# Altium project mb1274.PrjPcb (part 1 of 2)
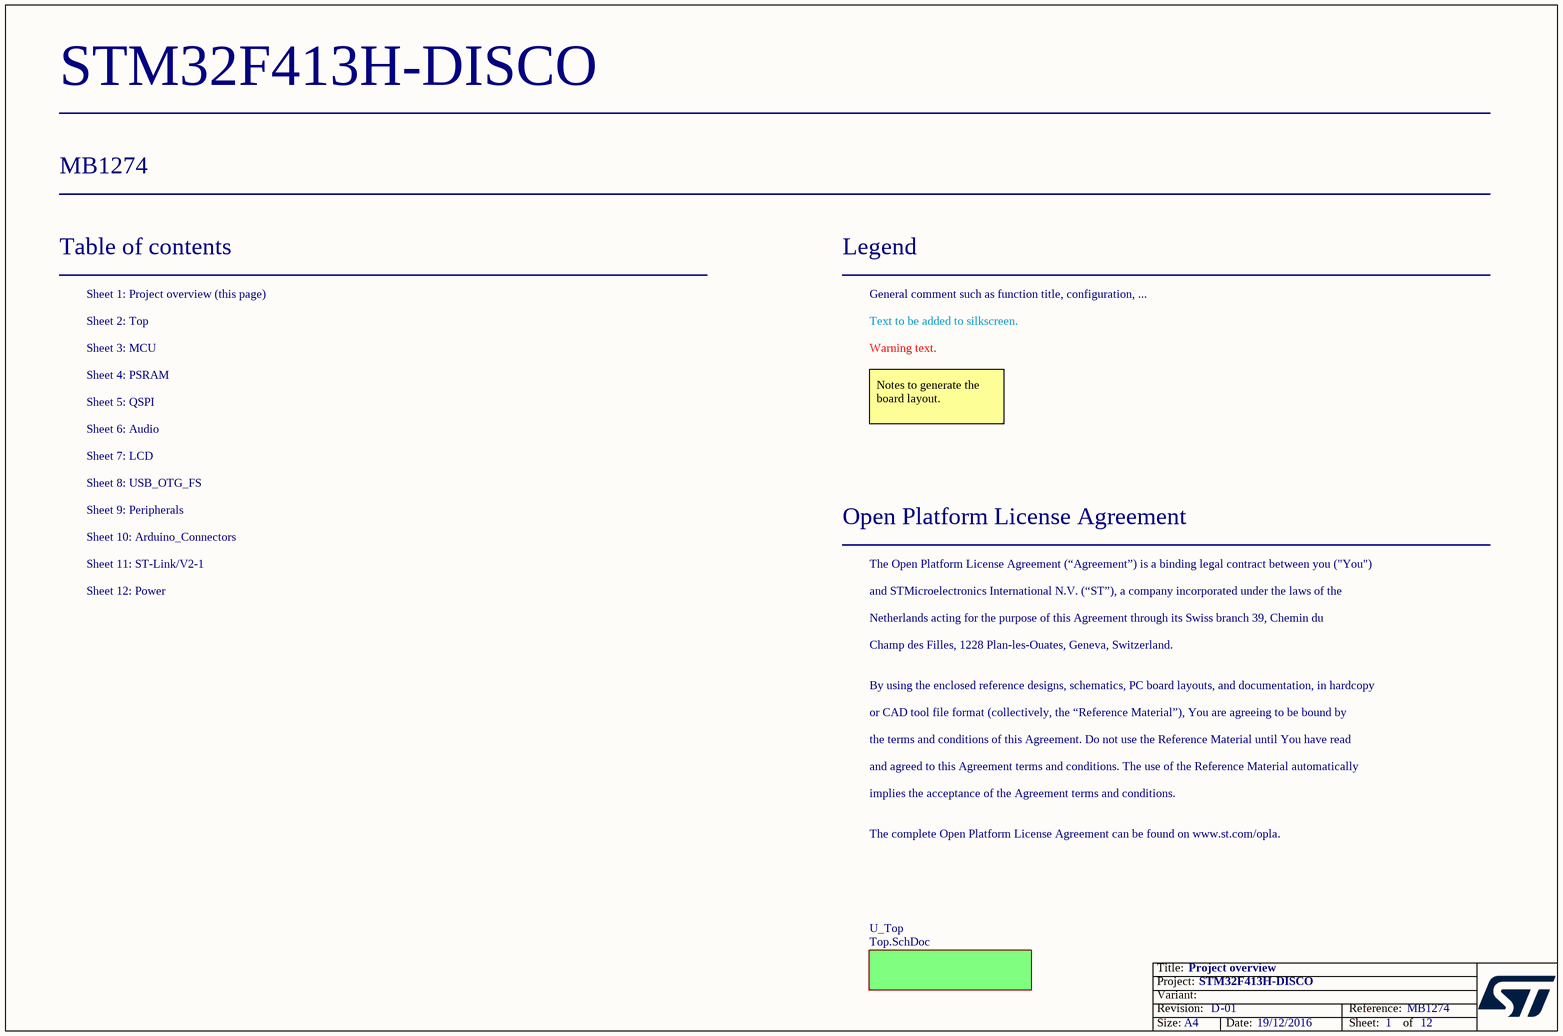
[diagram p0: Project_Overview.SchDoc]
Board_Assembly_Revision: 01; Board_Document_Date: 19/12/2016; Board_name: STM32F413H-DISCO; Board_PCB_Revision: D; Board_Reference: MB1274
12 sheets, 338 parts. Net scope: flat (ports and power ports of the same name join across sheets).
Sheets:
  Project_Overview.SchDoc
    U_Top = Top.SchDoc
      U_00_MCU = 00_MCU.SchDoc
      U_01_PSRAM = 01_PSRAM.SchDoc
      U_02_QSPI = 02_QSPI.SchDoc
      U_04_LCD = 04_LCD.SchDoc
      U_03_Audio = 03_Audio.SchDoc
      U_05_USB_OTG_FS = 05_USB_OTG_FS.SchDoc
      U_06_Peripherals = 06_Peripherals.SchDoc
      U_07_Arduino_ Connectors = 07_Arduino_ Connectors.SchDoc
      U_08_ST_LINK_V2-1 = 08_ST_LINK_V2-1.SCHDOC
      U_09_Power = 09_Power.SchDoc

## Sheet Project_Overview.SchDoc: Project overview
size A4; Date: Not used; ApprovedBy: Not used; CheckedBy: Not used; Author: Not used; CompanyName: STMicroelectronics; DrawnBy: Not used; Engineer: Not used; Organization: Not used; Address1: Not used; Address2: Not used; Address3: Not used; Address4: Not used; DocumentNumber: 1; Revision: Not used; SheetNumber: 1; SheetTotal: 12

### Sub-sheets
U_Top = Top.SchDoc: no entries

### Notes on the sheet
- Table of contents
- Sheet 1: Project overview (this page)
- Legend
- General comment such as function title, configuration, ...
- Sheet 2: Top
- Sheet 3: MCU
- Sheet 4: PSRAM
- Text to be added to silkscreen.
- Warning text.
- Sheet 6: Audio
- Sheet 5: QSPI
- Notes to generate the board layout.
- Sheet 7: LCD
- Sheet 8: USB_OTG_FS
- Sheet 9: Peripherals
- Sheet 11: ST-Link/V2-1
- Sheet 10: Arduino_Connectors
- Open Platform License Agreement
- The Open Platform License Agreement (“Agreement”) is a binding legal contract between you ("You")
- Sheet 12: Power
- and STMicroelectronics International N.V. (“ST”), a company incorporated under the laws of the
- Netherlands acting for the purpose of this Agreement through its Swiss branch 39, Chemin du
- Champ des Filles, 1228 Plan-les-Ouates, Geneva, Switzerland.
- By using the enclosed reference designs, schematics, PC board layouts, and documentation, in hardcopy
- or CAD tool file format (collectively, the “Reference Material”), You are agreeing to be bound by
- the terms and conditions of this Agreement. Do not use the Reference Material until You have read
- and agreed to this Agreement terms and conditions. The use of the Reference Material automatically
- implies the acceptance of the Agreement terms and conditions.
- The complete Open Platform License Agreement can be found on www.st.com/opla.

## Sheet Top.SchDoc: MB1274-TOP
size A3; Date: 3/31/2015; Author: P.A.; CompanyName: STMicroelectronics; Organization: Microcontrollers Division; Address1: 12, Rue Jules HOROWITZ; Address2: 38019 Grenoble; Address3: FRANCE; DocumentNumber: 2; Revision: D-01; SheetNumber: 2; SheetTotal: 12; Project: STM32F413H-DISCO
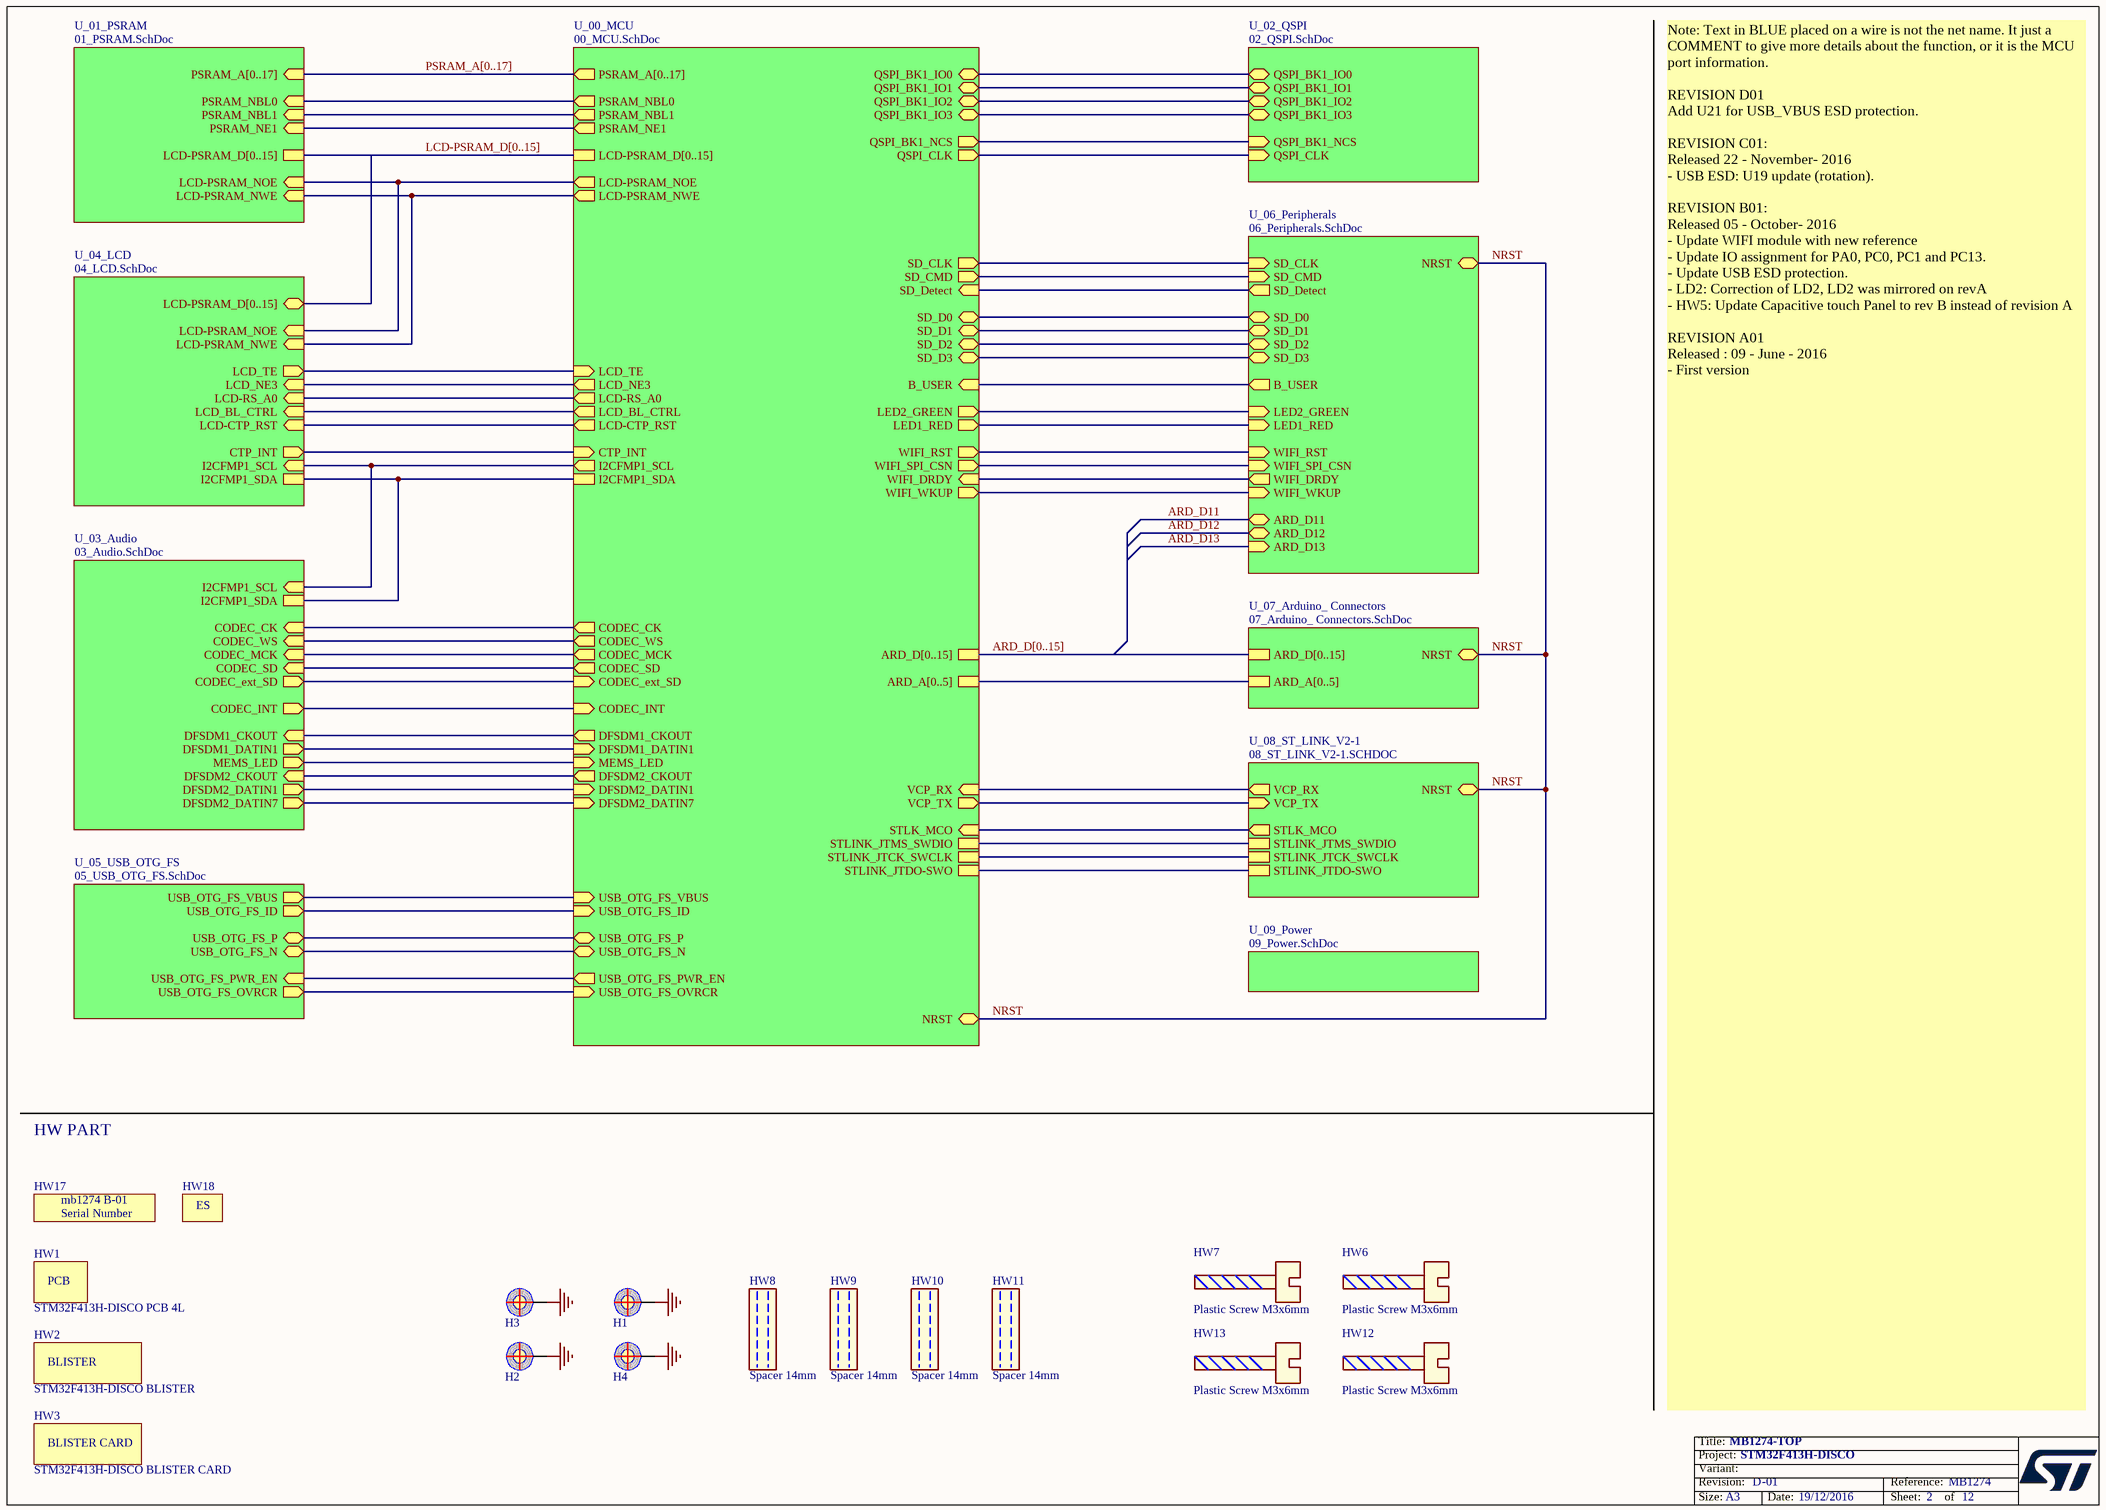
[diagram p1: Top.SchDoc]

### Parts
H1  POSITION HOLE C6D3R5  [PTH_M1261-3005-N_3P5X6_M3_H14]  (value not drawn)
H2  POSITION HOLE C6D3R5  [PTH_M1261-3005-N_3P5X6_M3_H14]  (value not drawn)
H3  POSITION HOLE C6D3R5  [PTH_M1261-3005-N_3P5X6_M3_H14]  (value not drawn)
H4  POSITION HOLE C6D3R5  [PTH_M1261-3005-N_3P5X6_M3_H14]  (value not drawn)
HW1  STM32F413H-DISCO PCB 4L  (mechanical)
HW2  STM32F413H-DISCO BLISTER  (mechanical)
HW3  STM32F413H-DISCO BLISTER CARD  (mechanical)
HW6  Plastic Screw M3x6mm  (mechanical)
HW7  Plastic Screw M3x6mm  (mechanical)
HW8  Spacer 14mm  (mechanical)
HW9  Spacer 14mm  (mechanical)
HW10  Spacer 14mm  (mechanical)
HW11  Spacer 14mm  (mechanical)
HW12  Plastic Screw M3x6mm  (mechanical)
HW13  Plastic Screw M3x6mm  (mechanical)
HW17  mb1274 B-01 + SN  (value not drawn)  (mechanical)
HW18  ES  (value not drawn)  (mechanical)

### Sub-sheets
U_00_MCU = 00_MCU.SchDoc: NRST (bidir), QSPI_BK1_IO3 (bidir), QSPI_BK1_IO2 (bidir), QSPI_BK1_IO0 (bidir), QSPI_BK1_IO1 (bidir), QSPI_CLK (out), QSPI_BK1_NCS (out), USB_OTG_FS_OVRCR (in), USB_OTG_FS_PWR_EN (out), B_USER (in), STLK_MCO (in), CODEC_INT (in), LCD_TE (in), LCD_BL_CTRL (out), PSRAM_A[0..17] (out), LCD-PSRAM_D[0..15], LCD-PSRAM_NWE (out), LCD-PSRAM_NOE (out), PSRAM_NE1 (out), PSRAM_NBL0 (out), PSRAM_NBL1 (out), LCD_NE3 (out), LCD-CTP_RST (out), CTP_INT (in), LED1_RED (out), LED2_GREEN (out), USB_OTG_FS_VBUS (in), USB_OTG_FS_ID (in), I2CFMP1_SDA, I2CFMP1_SCL (out), USB_OTG_FS_N (bidir), USB_OTG_FS_P (bidir), STLINK_JTMS_SWDIO, STLINK_JTCK_SWCLK, STLINK_JTDO-SWO, LCD-RS_A0 (out), SD_D2 (bidir), WIFI_SPI_CSN (out), DFSDM2_DATIN7 (in), WIFI_DRDY (in), SD_D3 (bidir), SD_CLK (out), DFSDM1_DATIN1 (in), DFSDM2_DATIN1 (in), DFSDM1_CKOUT (out), SD_Detect (in), SD_CMD (out), SD_D0 (bidir), SD_D1 (bidir), DFSDM2_CKOUT (out), CODEC_WS (out), CODEC_CK (out), CODEC_SD (out), CODEC_MCK (out), CODEC_ext_SD (in), ARD_A[0..5], ARD_D[0..15], VCP_TX (out), VCP_RX (in), WIFI_WKUP (out), MEMS_LED (in), WIFI_RST (out)
U_01_PSRAM = 01_PSRAM.SchDoc: PSRAM_A[0..17] (in), LCD-PSRAM_D[0..15], LCD-PSRAM_NWE (in), LCD-PSRAM_NOE (in), PSRAM_NE1 (in), PSRAM_NBL0 (in), PSRAM_NBL1 (in)
U_02_QSPI = 02_QSPI.SchDoc: QSPI_BK1_IO0 (bidir), QSPI_BK1_IO2 (bidir), QSPI_BK1_IO1 (bidir), QSPI_BK1_IO3 (bidir), QSPI_CLK (in), QSPI_BK1_NCS (in)
U_03_Audio = 03_Audio.SchDoc: CODEC_INT (out), I2CFMP1_SCL (in), I2CFMP1_SDA, DFSDM1_DATIN1 (out), DFSDM1_CKOUT (in), DFSDM2_CKOUT (in), DFSDM2_DATIN1 (out), DFSDM2_DATIN7 (out), CODEC_CK (in), CODEC_WS (in), CODEC_SD (in), CODEC_ext_SD (out), CODEC_MCK (in), MEMS_LED (out)
U_04_LCD = 04_LCD.SchDoc: LCD_BL_CTRL (in), CTP_INT (out), LCD_TE (out), LCD-CTP_RST (in), LCD_NE3 (in), LCD-PSRAM_D[0..15] (bidir), LCD-PSRAM_NWE (in), LCD-PSRAM_NOE (in), LCD-RS_A0 (in), I2CFMP1_SDA, I2CFMP1_SCL (in)
U_05_USB_OTG_FS = 05_USB_OTG_FS.SchDoc: USB_OTG_FS_VBUS (out), USB_OTG_FS_ID (out), USB_OTG_FS_PWR_EN (in), USB_OTG_FS_OVRCR (out), USB_OTG_FS_N (bidir), USB_OTG_FS_P (bidir)
U_06_Peripherals = 06_Peripherals.SchDoc: LED1_RED (in), LED2_GREEN (in), NRST (bidir), B_USER (out), SD_CLK (in), SD_CMD (in), SD_D0 (bidir), SD_D1 (bidir), SD_D2 (bidir), SD_D3 (bidir), SD_Detect (out), WIFI_SPI_CSN (in), WIFI_DRDY (out), WIFI_RST (in), WIFI_WKUP (in), ARD_D11 (bidir), ARD_D12 (bidir), ARD_D13 (in)
U_07_Arduino_ Connectors = 07_Arduino_ Connectors.SchDoc: NRST (bidir), ARD_A[0..5], ARD_D[0..15]
U_08_ST_LINK_V2-1 = 08_ST_LINK_V2-1.SCHDOC: NRST (bidir), STLINK_JTDO-SWO, STLK_MCO (out), STLINK_JTMS_SWDIO, STLINK_JTCK_SWCLK, VCP_RX (out), VCP_TX (in)
U_09_Power = 09_Power.SchDoc: no entries

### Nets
GND: H1.1 H2.1 H3.1 H4.1
NRST: sheet U_00_MCU/NRST, sheet U_06_Peripherals/NRST, sheet U_07_Arduino_ Connectors/NRST, sheet U_08_ST_LINK_V2-1/NRST
(unnamed): sheet U_00_MCU/QSPI_BK1_IO3, sheet U_02_QSPI/QSPI_BK1_IO3
(unnamed): sheet U_00_MCU/QSPI_BK1_IO2, sheet U_02_QSPI/QSPI_BK1_IO2  [a separate net that carries the same name]
(unnamed): sheet U_00_MCU/QSPI_BK1_IO0, sheet U_02_QSPI/QSPI_BK1_IO0  [a separate net that carries the same name]
(unnamed): sheet U_00_MCU/QSPI_BK1_IO1, sheet U_02_QSPI/QSPI_BK1_IO1  [a separate net that carries the same name]
(unnamed): sheet U_00_MCU/QSPI_CLK, sheet U_02_QSPI/QSPI_CLK  [a separate net that carries the same name]
(unnamed): sheet U_00_MCU/QSPI_BK1_NCS, sheet U_02_QSPI/QSPI_BK1_NCS  [a separate net that carries the same name]
(unnamed): sheet U_00_MCU/USB_OTG_FS_OVRCR, sheet U_05_USB_OTG_FS/USB_OTG_FS_OVRCR  [a separate net that carries the same name]
(unnamed): sheet U_00_MCU/USB_OTG_FS_PWR_EN, sheet U_05_USB_OTG_FS/USB_OTG_FS_PWR_EN  [a separate net that carries the same name]
(unnamed): sheet U_00_MCU/B_USER, sheet U_06_Peripherals/B_USER  [a separate net that carries the same name]
(unnamed): sheet U_00_MCU/STLK_MCO, sheet U_08_ST_LINK_V2-1/STLK_MCO  [a separate net that carries the same name]
(unnamed): sheet U_00_MCU/CODEC_INT, sheet U_03_Audio/CODEC_INT  [a separate net that carries the same name]
(unnamed): sheet U_00_MCU/LCD_TE, sheet U_04_LCD/LCD_TE  [a separate net that carries the same name]
(unnamed): sheet U_00_MCU/LCD_BL_CTRL, sheet U_04_LCD/LCD_BL_CTRL  [a separate net that carries the same name]
(unnamed): sheet U_00_MCU/LCD-PSRAM_NWE, sheet U_01_PSRAM/LCD-PSRAM_NWE, sheet U_04_LCD/LCD-PSRAM_NWE  [a separate net that carries the same name]
(unnamed): sheet U_00_MCU/LCD-PSRAM_NOE, sheet U_01_PSRAM/LCD-PSRAM_NOE, sheet U_04_LCD/LCD-PSRAM_NOE  [a separate net that carries the same name]
(unnamed): sheet U_00_MCU/PSRAM_NE1, sheet U_01_PSRAM/PSRAM_NE1  [a separate net that carries the same name]
(unnamed): sheet U_00_MCU/PSRAM_NBL0, sheet U_01_PSRAM/PSRAM_NBL0  [a separate net that carries the same name]
(unnamed): sheet U_00_MCU/PSRAM_NBL1, sheet U_01_PSRAM/PSRAM_NBL1  [a separate net that carries the same name]
(unnamed): sheet U_00_MCU/LCD_NE3, sheet U_04_LCD/LCD_NE3  [a separate net that carries the same name]
(unnamed): sheet U_00_MCU/LCD-CTP_RST, sheet U_04_LCD/LCD-CTP_RST  [a separate net that carries the same name]
(unnamed): sheet U_00_MCU/CTP_INT, sheet U_04_LCD/CTP_INT  [a separate net that carries the same name]
(unnamed): sheet U_00_MCU/LED1_RED, sheet U_06_Peripherals/LED1_RED  [a separate net that carries the same name]
(unnamed): sheet U_00_MCU/LED2_GREEN, sheet U_06_Peripherals/LED2_GREEN  [a separate net that carries the same name]
(unnamed): sheet U_00_MCU/USB_OTG_FS_VBUS, sheet U_05_USB_OTG_FS/USB_OTG_FS_VBUS  [a separate net that carries the same name]
(unnamed): sheet U_00_MCU/USB_OTG_FS_ID, sheet U_05_USB_OTG_FS/USB_OTG_FS_ID  [a separate net that carries the same name]
(unnamed): sheet U_00_MCU/I2CFMP1_SDA, sheet U_04_LCD/I2CFMP1_SDA, sheet U_03_Audio/I2CFMP1_SDA  [a separate net that carries the same name]
(unnamed): sheet U_00_MCU/I2CFMP1_SCL, sheet U_04_LCD/I2CFMP1_SCL, sheet U_03_Audio/I2CFMP1_SCL  [a separate net that carries the same name]
(unnamed): sheet U_00_MCU/USB_OTG_FS_N, sheet U_05_USB_OTG_FS/USB_OTG_FS_N  [a separate net that carries the same name]
(unnamed): sheet U_00_MCU/USB_OTG_FS_P, sheet U_05_USB_OTG_FS/USB_OTG_FS_P  [a separate net that carries the same name]
(unnamed): sheet U_00_MCU/STLINK_JTMS_SWDIO, sheet U_08_ST_LINK_V2-1/STLINK_JTMS_SWDIO  [a separate net that carries the same name]
(unnamed): sheet U_00_MCU/STLINK_JTCK_SWCLK, sheet U_08_ST_LINK_V2-1/STLINK_JTCK_SWCLK  [a separate net that carries the same name]
(unnamed): sheet U_00_MCU/STLINK_JTDO-SWO, sheet U_08_ST_LINK_V2-1/STLINK_JTDO-SWO  [a separate net that carries the same name]
(unnamed): sheet U_00_MCU/LCD-RS_A0, sheet U_04_LCD/LCD-RS_A0  [a separate net that carries the same name]
(unnamed): sheet U_00_MCU/SD_D2, sheet U_06_Peripherals/SD_D2  [a separate net that carries the same name]
(unnamed): sheet U_00_MCU/WIFI_SPI_CSN, sheet U_06_Peripherals/WIFI_SPI_CSN  [a separate net that carries the same name]
(unnamed): sheet U_00_MCU/DFSDM2_DATIN7, sheet U_03_Audio/DFSDM2_DATIN7  [a separate net that carries the same name]
(unnamed): sheet U_00_MCU/WIFI_DRDY, sheet U_06_Peripherals/WIFI_DRDY  [a separate net that carries the same name]
(unnamed): sheet U_00_MCU/SD_D3, sheet U_06_Peripherals/SD_D3  [a separate net that carries the same name]
(unnamed): sheet U_00_MCU/SD_CLK, sheet U_06_Peripherals/SD_CLK  [a separate net that carries the same name]
(unnamed): sheet U_00_MCU/DFSDM1_DATIN1, sheet U_03_Audio/DFSDM1_DATIN1  [a separate net that carries the same name]
(unnamed): sheet U_00_MCU/DFSDM2_DATIN1, sheet U_03_Audio/DFSDM2_DATIN1  [a separate net that carries the same name]
(unnamed): sheet U_00_MCU/DFSDM1_CKOUT, sheet U_03_Audio/DFSDM1_CKOUT  [a separate net that carries the same name]
(unnamed): sheet U_00_MCU/SD_Detect, sheet U_06_Peripherals/SD_Detect  [a separate net that carries the same name]
(unnamed): sheet U_00_MCU/SD_CMD, sheet U_06_Peripherals/SD_CMD  [a separate net that carries the same name]
(unnamed): sheet U_00_MCU/SD_D0, sheet U_06_Peripherals/SD_D0  [a separate net that carries the same name]
(unnamed): sheet U_00_MCU/SD_D1, sheet U_06_Peripherals/SD_D1  [a separate net that carries the same name]
(unnamed): sheet U_00_MCU/DFSDM2_CKOUT, sheet U_03_Audio/DFSDM2_CKOUT  [a separate net that carries the same name]
(unnamed): sheet U_00_MCU/CODEC_WS, sheet U_03_Audio/CODEC_WS  [a separate net that carries the same name]
(unnamed): sheet U_00_MCU/CODEC_CK, sheet U_03_Audio/CODEC_CK  [a separate net that carries the same name]
(unnamed): sheet U_00_MCU/CODEC_SD, sheet U_03_Audio/CODEC_SD  [a separate net that carries the same name]
(unnamed): sheet U_00_MCU/CODEC_MCK, sheet U_03_Audio/CODEC_MCK  [a separate net that carries the same name]
(unnamed): sheet U_00_MCU/CODEC_ext_SD, sheet U_03_Audio/CODEC_ext_SD  [a separate net that carries the same name]
(unnamed): sheet U_00_MCU/VCP_TX, sheet U_08_ST_LINK_V2-1/VCP_TX  [a separate net that carries the same name]
(unnamed): sheet U_00_MCU/VCP_RX, sheet U_08_ST_LINK_V2-1/VCP_RX  [a separate net that carries the same name]
(unnamed): sheet U_00_MCU/WIFI_WKUP, sheet U_06_Peripherals/WIFI_WKUP  [a separate net that carries the same name]
(unnamed): sheet U_00_MCU/MEMS_LED, sheet U_03_Audio/MEMS_LED  [a separate net that carries the same name]
(unnamed): sheet U_00_MCU/WIFI_RST, sheet U_06_Peripherals/WIFI_RST  [a separate net that carries the same name]

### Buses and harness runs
bus ARD_D[0..15] = sheet U_00_MCU/ARD_D[0..15] = sheet U_07_Arduino_ Connectors/ARD_D[0..15]
bus LCD-PSRAM_D[0..15] = sheet U_00_MCU/LCD-PSRAM_D[0..15] = sheet U_01_PSRAM/LCD-PSRAM_D[0..15] = sheet U_04_LCD/LCD-PSRAM_D[0..15]
bus PSRAM_A[0..17] = sheet U_00_MCU/PSRAM_A[0..17] = sheet U_01_PSRAM/PSRAM_A[0..17]
bus sheet U_00_MCU/ARD_A[0..5] = sheet U_07_Arduino_ Connectors/ARD_A[0..5]

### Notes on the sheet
- HW PART
- Note: Text in BLUE placed on a wire is not the net name. It just a COMMENT to give more details about the function, or it is the MCU port information.
  REVISION D01
  Add U21 for USB_VBUS ESD protection.
  REVISION C01:
  Released 22 - November- 2016
  - USB ESD: U19 update (rotation).
  REVISION B01:
  Released 05 - October- 2016
  - Update WIFI module with new reference
  - Update IO assignment for PA0, PC0, PC1 and PC13.
  - Update USB ESD protection.
  - LD2: Correction of LD2, LD2 was mirrored on revA
  - HW5: Update Capacitive touch Panel to rev B instead of revision A
  REVISION A01
  Released : 09 - June - 2016
  - First version

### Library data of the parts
HW1 = PCB: Fitted: YES; Ordered_By: Subcon
HW2 = BLISTER: Fitted: YES; Ordered_By: Subcon
HW3 = BLISTER CARD: Ordered_By: subcon; Fitted: YES
HW6 HW7 HW12 HW13 = Plastic Screw M3x6mm: Plastic screw; Ordered_By: Subcon; Fitted: Manually
HW8-HW11 = Plastic Spacer D4.5x14, M3x0.5: Plastic spacer; Manuf_1: RAF; Manuf_Part_1: M1261-3005-N; Ordered_By: Subcon; Fitted: Manually
HW17 = STICKER_SN_number: Sticker for Board SN number; Ordered_By: Subcon; Fitted: YES
HW18 = STICKER_ES: Sticker for ES sample; Ordered_By: Subcon; Fitted: YES

## Sheet 00_MCU.SchDoc: MCU
size A3; Date: 3/31/2015; Author: P.A.; CompanyName: STMicroelectronics; Organization: Microcontrollers Division; Address1: 12, Rue Jules HOROWITZ; Address2: 38019 Grenoble; Address3: FRANCE; DocumentNumber: 3; Revision: D-01; SheetNumber: 3; SheetTotal: 12; Project: STM32F413H-DISCO
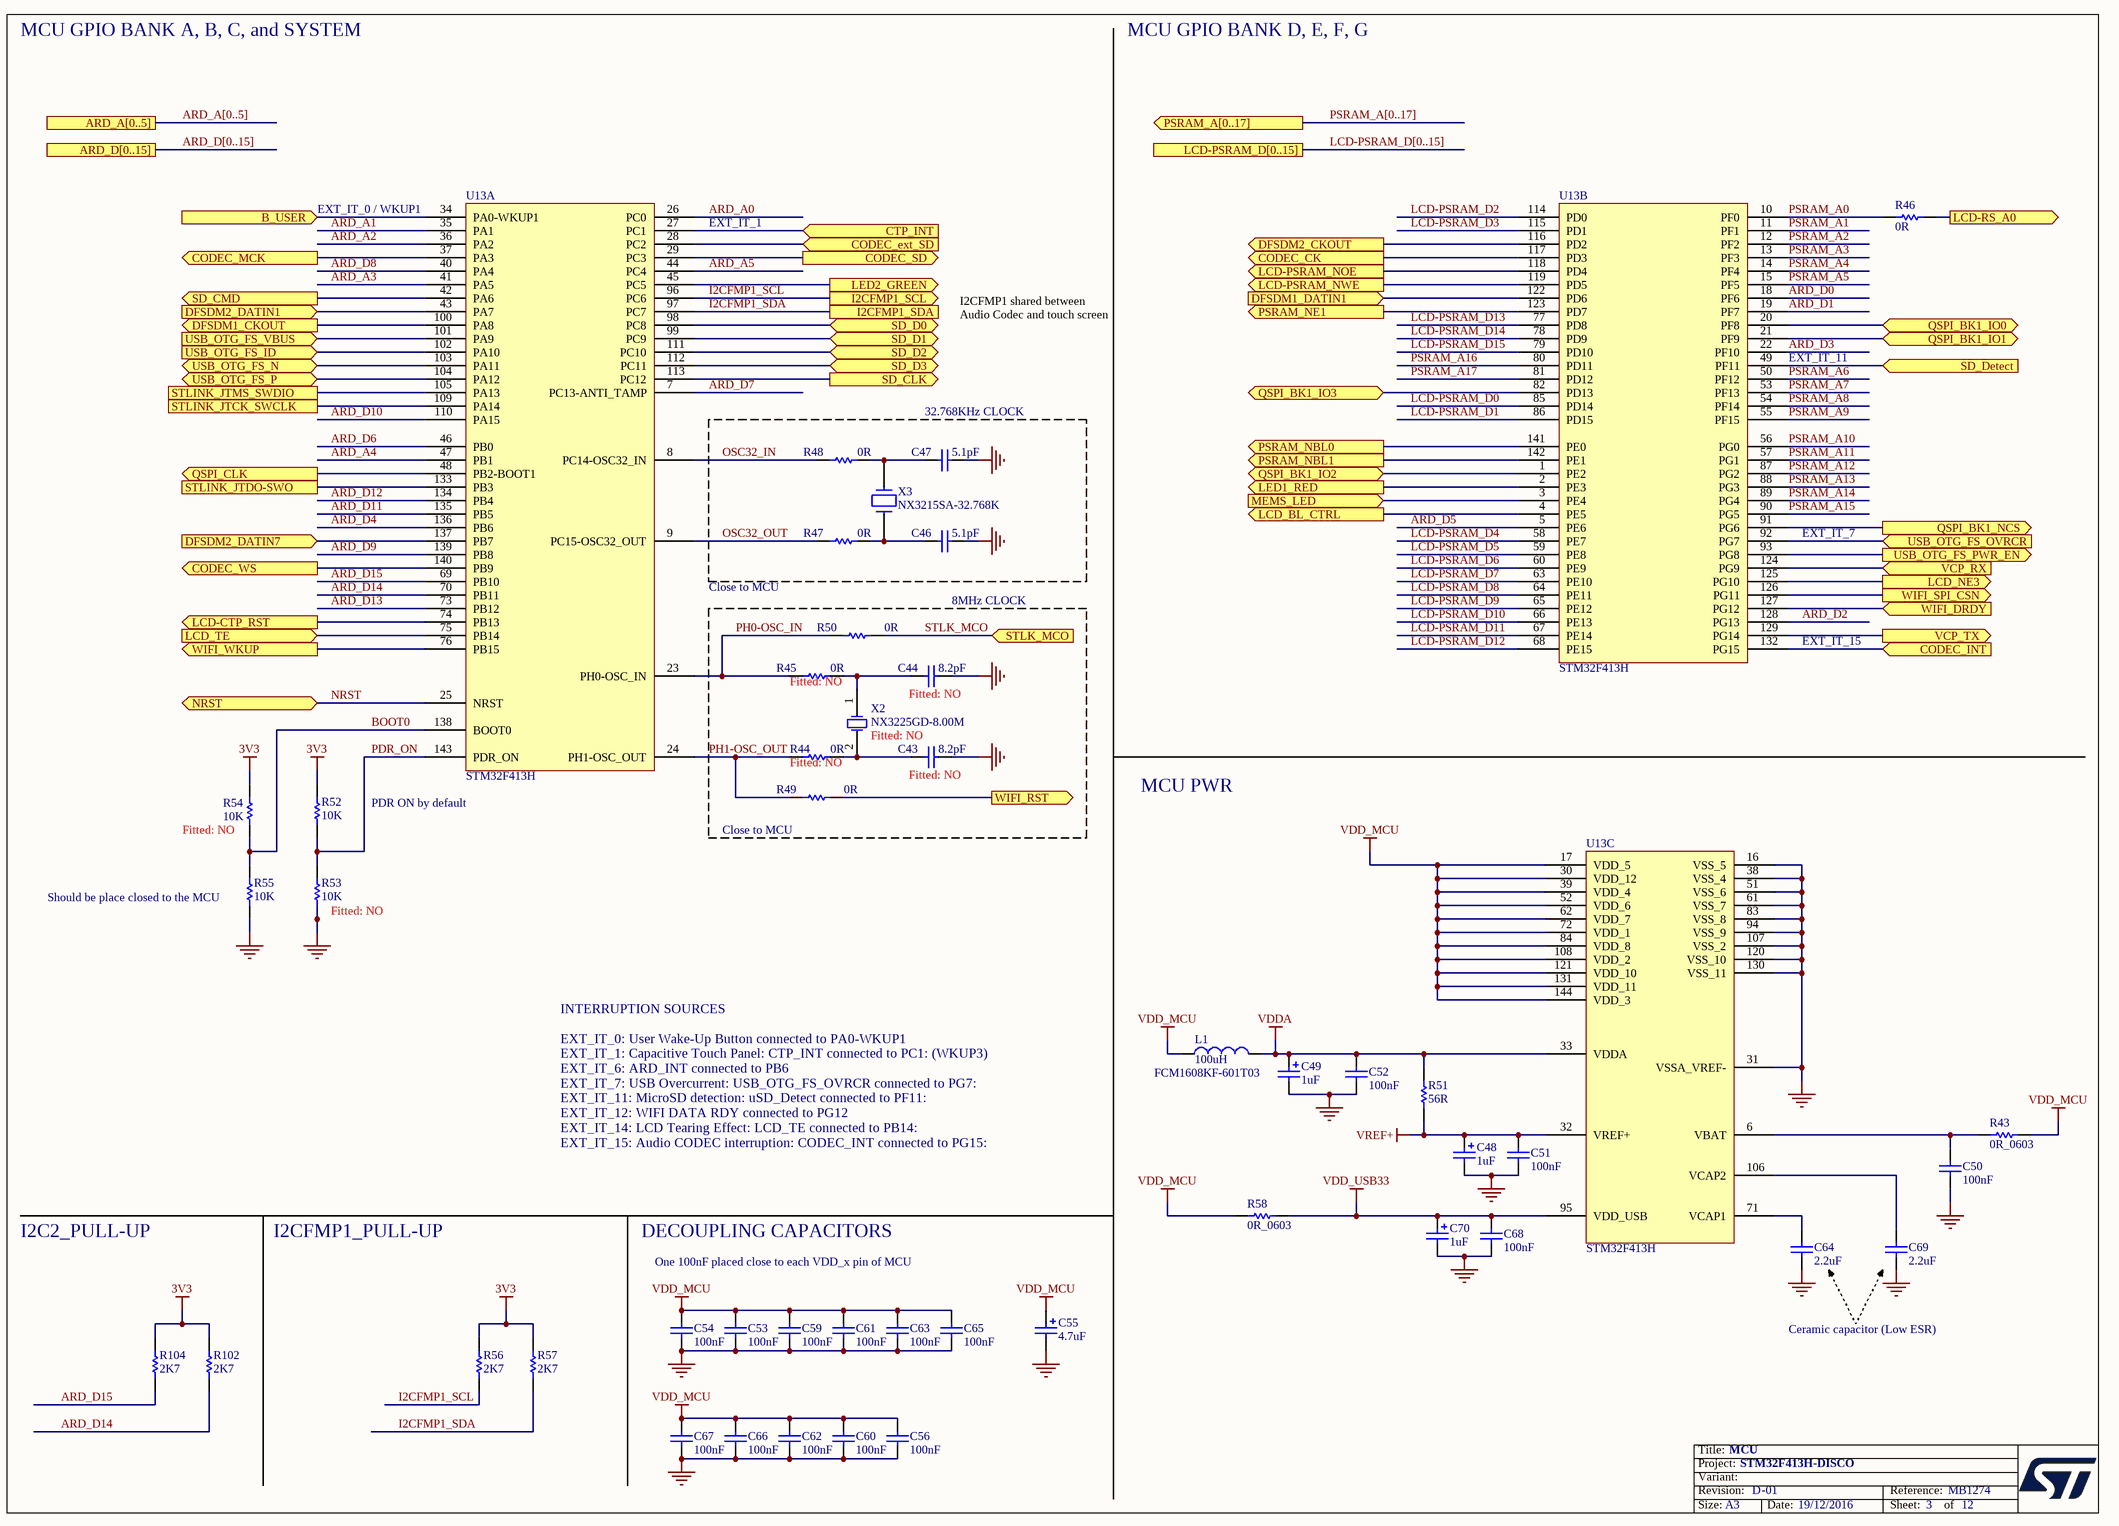
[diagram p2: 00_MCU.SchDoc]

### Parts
C43  8.2pF  Fitted: NO  [C0402]
C44  8.2pF  Fitted: NO  [C0402]
C46  5.1pF  [C0402]
C47  5.1pF  [C0402]
C48  1uF  [CPOL_TAJ-A_1206_H180]
C49  1uF  [CPOL_TAJ-A_1206_H180]
C50  100nF  [C0402]
C51  100nF  [C0402]
C52  100nF  [C0402]
C53  100nF  [C0402]
C54  100nF  [C0402]
C55  4.7uF  [CPOL_TAJ-A_1206_H180]
C56  100nF  [C0402]
C59  100nF  [C0402]
C60  100nF  [C0402]
C61  100nF  [C0402]
C62  100nF  [C0402]
C63  100nF  [C0402]
C64  2.2uF  [C1206]
C65  100nF  [C0402]
C66  100nF  [C0402]
C67  100nF  [C0402]
C68  100nF  [C0402]
C69  2.2uF  [C1206]
C70  1uF  [CPOL_TAJ-A_1206_H180]
L1  100uH  Manuf_Part_1: FCM1608KF-601T03  [L0603]
R43  0R_0603  [R0603]
R44  0R  Fitted: NO  [R0402]
R45  0R  Fitted: NO  [R0402]
R46  0R  [R0402]
R47  0R  [R0402]
R48  0R  [R0402]
R49  0R  [R0402]
R50  0R  [R0402]
R51  56R  [R0402]
R52  10K  [R0402]
R53  10K  Fitted: NO  [R0402]
R54  10K  Fitted: NO  [R0402]
R55  10K  [R0402]
R56  2K7  [R0402]
R57  2K7  [R0402]
R58  0R_0603  [R0603]
R102  2K7  [R0402]
R104  2K7  [R0402]
U13  STM32F413H  [ICC_LQFP144_20X20_P050]  (parts A,B,C of 3)
X2  NX3225GD-8.00M  Fitted: NO  [CRY_NX3225GD_2P]
X3  NX3215SA-32.768K  [CRY_NX3215SA_2P]

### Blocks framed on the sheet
32.768KHz CLOCK: C46 C47 R47 R48 X3

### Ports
ARD_A[0..5], ARD_D[0..15], B_USER (in), CODEC_CK (out), CODEC_ext_SD (in), CODEC_INT (in), CODEC_MCK (out), CODEC_SD (out), CODEC_WS (out), CTP_INT (in), DFSDM1_CKOUT (out), DFSDM1_DATIN1 (in), DFSDM2_CKOUT (out), DFSDM2_DATIN1 (in), DFSDM2_DATIN7 (in), I2CFMP1_SCL (out), I2CFMP1_SDA, LCD-CTP_RST (out), LCD-PSRAM_D[0..15], LCD-PSRAM_NOE (out), LCD-PSRAM_NWE (out), LCD-RS_A0 (out), LCD_BL_CTRL (out), LCD_NE3 (out), LCD_TE (in), LED1_RED (out), LED2_GREEN (out), MEMS_LED (in), NRST (bidir), PSRAM_A[0..17] (out), PSRAM_NBL0 (out), PSRAM_NBL1 (out), PSRAM_NE1 (out), QSPI_BK1_IO0 (bidir), QSPI_BK1_IO1 (bidir), QSPI_BK1_IO2 (bidir), QSPI_BK1_IO3 (bidir), QSPI_BK1_NCS (out), QSPI_CLK (out), SD_CLK (out), SD_CMD (out), SD_D0 (bidir), SD_D1 (bidir), SD_D2 (bidir), SD_D3 (bidir), SD_Detect (in), STLINK_JTCK_SWCLK, STLINK_JTDO-SWO, STLINK_JTMS_SWDIO, STLK_MCO (in), USB_OTG_FS_ID (in), USB_OTG_FS_N (bidir), USB_OTG_FS_OVRCR (in), USB_OTG_FS_P (bidir), USB_OTG_FS_PWR_EN (out), USB_OTG_FS_VBUS (in), VCP_RX (in), VCP_TX (out), WIFI_DRDY (in), WIFI_RST (out), WIFI_SPI_CSN (out), WIFI_WKUP (out)

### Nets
3V3: R52.2 R54.1 R56.2 R57.2 R102.2 R104.2
GND: C43.2 C44.2 C46.2 C47.2 C48.2 C49.2 C50.1 C51.1 C52.1 C53.1 C54.1 C55.2 C56.1 C59.1 C60.1 C61.1 C62.1 C63.1 C64.1 C65.1 C66.1 C67.1 C68.1 C69.1 C70.2 R53.1 R55.1 U13.16(VSS_5) U13.31(VSSA_VREF-) U13.38(VSS_4) U13.51(VSS_6) U13.61(VSS_7) U13.83(VSS_8) U13.94(VSS_9) U13.107(VSS_2) U13.120(VSS_10) U13.130(VSS_11)
VDD_MCU: C53.2 C54.2 C55.1 C56.2 C59.2 C60.2 C61.2 C62.2 C63.2 C65.2 C66.2 C67.2 L1.1 R43.2 R58.1 U13.17(VDD_5) U13.30(VDD_12) U13.39(VDD_4) U13.52(VDD_6) U13.62(VDD_7) U13.72(VDD_1) U13.84(VDD_8) U13.108(VDD_2) U13.121(VDD_10) U13.131(VDD_11) U13.144(VDD_3)
VDD_USB33: C68.2 C70.1 R58.2 U13.95(VDD_USB)
VDDA: C49.1 C52.2 L1.2 R51.2 U13.33(VDDA)
VREF+: C48.1 C51.2 R51.1 U13.32(VREF+)
ARD_A0: U13.26(PC0)
ARD_A1: U13.35(PA1)
ARD_A2: U13.36(PA2)
ARD_A3: U13.41(PA5)
ARD_A4: U13.47(PB1)
ARD_A5: U13.44(PC4)
ARD_D0: U13.18(PF6)
ARD_D1: U13.19(PF7)
ARD_D2: U13.128(PG13)
ARD_D3: U13.22(PF10)
ARD_D4: U13.136(PB6)
ARD_D5: U13.5(PE6)
ARD_D6: U13.46(PB0)
ARD_D7: U13.7(PC13-ANTI_TAMP)
ARD_D8: U13.40(PA4)
ARD_D9: U13.139(PB8)
ARD_D10: U13.110(PA15)
ARD_D11: U13.135(PB5)
ARD_D12: U13.134(PB4)
ARD_D13: U13.73(PB12)
ARD_D14: R102.1 U13.70(PB11)
ARD_D15: R104.1 U13.69(PB10)
B_USER: U13.34(PA0-WKUP1) ; port B_USER
BOOT0: R54.2 R55.2 U13.138(BOOT0)
CODEC_CK: U13.117(PD3) ; port CODEC_CK
CODEC_ext_SD: U13.28(PC2) ; port CODEC_ext_SD
CODEC_INT: U13.132(PG15) ; port CODEC_INT
CODEC_MCK: U13.37(PA3) ; port CODEC_MCK
CODEC_SD: U13.29(PC3) ; port CODEC_SD
CODEC_WS: U13.140(PB9) ; port CODEC_WS
CTP_INT: U13.27(PC1) ; port CTP_INT
DFSDM1_CKOUT: U13.100(PA8) ; port DFSDM1_CKOUT
DFSDM1_DATIN1: U13.122(PD6) ; port DFSDM1_DATIN1
DFSDM2_CKOUT: U13.116(PD2) ; port DFSDM2_CKOUT
DFSDM2_DATIN1: U13.43(PA7) ; port DFSDM2_DATIN1
DFSDM2_DATIN7: U13.137(PB7) ; port DFSDM2_DATIN7
I2CFMP1_SCL: R56.1 U13.96(PC6) ; port I2CFMP1_SCL
I2CFMP1_SDA: R57.1 U13.97(PC7) ; port I2CFMP1_SDA
LCD-CTP_RST: U13.74(PB13) ; port LCD-CTP_RST
LCD-PSRAM_D0: U13.85(PD14)
LCD-PSRAM_D1: U13.86(PD15)
LCD-PSRAM_D2: U13.114(PD0)
LCD-PSRAM_D3: U13.115(PD1)
LCD-PSRAM_D4: U13.58(PE7)
LCD-PSRAM_D5: U13.59(PE8)
LCD-PSRAM_D6: U13.60(PE9)
LCD-PSRAM_D7: U13.63(PE10)
LCD-PSRAM_D8: U13.64(PE11)
LCD-PSRAM_D9: U13.65(PE12)
LCD-PSRAM_D10: U13.66(PE13)
LCD-PSRAM_D11: U13.67(PE14)
LCD-PSRAM_D12: U13.68(PE15)
LCD-PSRAM_D13: U13.77(PD8)
LCD-PSRAM_D14: U13.78(PD9)
LCD-PSRAM_D15: U13.79(PD10)
LCD-PSRAM_NOE: U13.118(PD4) ; port LCD-PSRAM_NOE
LCD-PSRAM_NWE: U13.119(PD5) ; port LCD-PSRAM_NWE
LCD-RS_A0: R46.2 ; port LCD-RS_A0
LCD_BL_CTRL: U13.4(PE5) ; port LCD_BL_CTRL
LCD_NE3: U13.125(PG10) ; port LCD_NE3
LCD_TE: U13.75(PB14) ; port LCD_TE
LED1_RED: U13.2(PE3) ; port LED1_RED
LED2_GREEN: U13.45(PC5) ; port LED2_GREEN
MEMS_LED: U13.3(PE4) ; port MEMS_LED
NRST: U13.25(NRST) ; port NRST
OSC32_IN: R48.1 U13.8(PC14-OSC32_IN)
OSC32_OUT: R47.1 U13.9(PC15-OSC32_OUT)
PDR_ON: R52.1 R53.2 U13.143(PDR_ON)
PH0-OSC_IN: R45.1 R50.1 U13.23(PH0-OSC_IN)
PH1-OSC_OUT: R44.1 R49.1 U13.24(PH1-OSC_OUT)
PSRAM_A0: R46.1 U13.10(PF0)
PSRAM_A1: U13.11(PF1)
PSRAM_A2: U13.12(PF2)
PSRAM_A3: U13.13(PF3)
PSRAM_A4: U13.14(PF4)
PSRAM_A5: U13.15(PF5)
PSRAM_A6: U13.50(PF12)
PSRAM_A7: U13.53(PF13)
PSRAM_A8: U13.54(PF14)
PSRAM_A9: U13.55(PF15)
PSRAM_A10: U13.56(PG0)
PSRAM_A11: U13.57(PG1)
PSRAM_A12: U13.87(PG2)
PSRAM_A13: U13.88(PG3)
PSRAM_A14: U13.89(PG4)
PSRAM_A15: U13.90(PG5)
PSRAM_A16: U13.80(PD11)
PSRAM_A17: U13.81(PD12)
PSRAM_NBL0: U13.141(PE0) ; port PSRAM_NBL0
PSRAM_NBL1: U13.142(PE1) ; port PSRAM_NBL1
PSRAM_NE1: U13.123(PD7) ; port PSRAM_NE1
QSPI_BK1_IO0: U13.20(PF8) ; port QSPI_BK1_IO0
QSPI_BK1_IO1: U13.21(PF9) ; port QSPI_BK1_IO1
QSPI_BK1_IO2: U13.1(PE2) ; port QSPI_BK1_IO2
QSPI_BK1_IO3: U13.82(PD13) ; port QSPI_BK1_IO3
QSPI_BK1_NCS: U13.91(PG6) ; port QSPI_BK1_NCS
QSPI_CLK: U13.48(PB2-BOOT1) ; port QSPI_CLK
SD_CLK: U13.113(PC12) ; port SD_CLK
SD_CMD: U13.42(PA6) ; port SD_CMD
SD_D0: U13.98(PC8) ; port SD_D0
SD_D1: U13.99(PC9) ; port SD_D1
SD_D2: U13.111(PC10) ; port SD_D2
SD_D3: U13.112(PC11) ; port SD_D3
SD_Detect: U13.49(PF11) ; port SD_Detect
STLINK_JTCK_SWCLK: U13.109(PA14) ; port STLINK_JTCK_SWCLK
STLINK_JTDO-SWO: U13.133(PB3) ; port STLINK_JTDO-SWO
STLINK_JTMS_SWDIO: U13.105(PA13) ; port STLINK_JTMS_SWDIO
STLK_MCO: R50.2 ; port STLK_MCO
USB_OTG_FS_ID: U13.102(PA10) ; port USB_OTG_FS_ID
USB_OTG_FS_N: U13.103(PA11) ; port USB_OTG_FS_N
USB_OTG_FS_OVRCR: U13.92(PG7) ; port USB_OTG_FS_OVRCR
USB_OTG_FS_P: U13.104(PA12) ; port USB_OTG_FS_P
USB_OTG_FS_PWR_EN: U13.93(PG8) ; port USB_OTG_FS_PWR_EN
USB_OTG_FS_VBUS: U13.101(PA9) ; port USB_OTG_FS_VBUS
VCP_RX: U13.124(PG9) ; port VCP_RX
VCP_TX: U13.129(PG14) ; port VCP_TX
WIFI_DRDY: U13.127(PG12) ; port WIFI_DRDY
WIFI_RST: R49.2 ; port WIFI_RST
WIFI_SPI_CSN: U13.126(PG11) ; port WIFI_SPI_CSN
WIFI_WKUP: U13.76(PB15) ; port WIFI_WKUP
NetC43_1: C43.1 R44.2 X2.2(OSC2)
NetC44_1: C44.1 R45.2 X2.1(OSC1)
NetC46_1: C46.1 R47.2 X3.2
NetC47_1: C47.1 R48.2 X3.1
NetC50_2: C50.2 R43.1 U13.6(VBAT)
NetC64_2: C64.2 U13.71(VCAP1)
NetC69_2: C69.2 U13.106(VCAP2)

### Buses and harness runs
bus ARD_A[0..5] = port ARD_A[0..5]
bus ARD_D[0..15] = port ARD_D[0..15]
bus LCD-PSRAM_D[0..15] = port LCD-PSRAM_D[0..15]
bus PSRAM_A[0..17] = port PSRAM_A[0..17]

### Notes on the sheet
- MCU GPIO BANK A, B, C, and SYSTEM
- MCU GPIO BANK D, E, F, G
- (near U13) EXT_IT_0 / WKUP1
- EXT_IT_1
- I2CFMP1 shared between
  Audio Codec and touch screen
- (near U13) EXT_IT_11
- Close to MCU
- EXT_IT_7
- 8MHz CLOCK
- EXT_IT_15
- MCU PWR
- PDR ON by default
- (near R49) Close to MCU
- (near R55) Should be place closed to the MCU
- INTERRUPTION SOURCES
  EXT_IT_0: User Wake-Up Button connected to PA0-WKUP1
  EXT_IT_1: Capacitive Touch Panel: CTP_INT connected to PC1: (WKUP3)
  EXT_IT_6: ARD_INT connected to PB6
  EXT_IT_7: USB Overcurrent: USB_OTG_FS_OVRCR connected to PG7:
  EXT_IT_11: MicroSD detection: uSD_Detect connected to PF11:
  EXT_IT_12: WIFI DATA RDY connected to PG12
  EXT_IT_14: LCD Tearing Effect: LCD_TE connected to PB14:
  EXT_IT_15: Audio CODEC interruption: CODEC_INT connected to PG15:
- I2C2_PULL-UP
- I2CFMP1_PULL-UP
- DECOUPLING CAPACITORS
- One 100nF placed close to each VDD_x pin of MCU
- Ceramic capacitor (Low ESR)

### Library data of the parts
C43 C44 = Cap_8.2pF_NPO_4%_0402: Capacitor,8.2pF,50V,NPO,4%,0402,AVX; Manuf_Part_1: 04025A8R2CAT2A; Ordered_By: Subcon
C46 C47 = Cap_5.1pF_NPO_-+0.25pF_0402: Capacitor, 5.1pF, 50V, NPO, -+0.25pF, 0402, YAGEO; Manuf_Part_1: CC0402CRNPO9BN5R1; Fitted: YES; Order_code: 311-1633-2-ND; Ordered_By: Subcon
C48 C49 C70 = Cap_1uF_POL_10%_TANA: Polarized Capacitor,1uF,16V,10%,typeA,AVX; Manuf_Part_1: TAJA105K016R; Fitted: YES; Ordered_By: Subcon
C50-C54 C56 C59-C63 C65-C68 = Cap_100nF_X7R_10%_0402: Capacitor,100nF,16V,X7R,10%,0402,YAGEO; Manuf_Part_1: CC0402KRX7R7BB104; Fitted: YES; Ordered_By: Subcon
C55 = Cap_4.7uF_POL_10%_TANA: Polarized Capacitor,4.7uF,16V,10%,typeA,AVX; Manuf_Part_1: TAJA475K016R; Fitted: YES; Ordered_By: Subcon
C64 C69 = Cap_2.2uF_X7R_10%_1206: Capacitor,2.2uF,16V, X7R,10%,1206,YAGEO; Manuf_Part_1: CC1206KKX7R7BB225; Manuf_Part_2: C1206C225K4RAC; Manuf_2: KEMET; Fitted: YES; Ordered_By: Subcon
L1 = BEAD_600R_350MA_0603: Bead,600R,350mA,0603; Manuf_2: TDK; Manuf_Part_2: MPZ1608S300A; Manuf_1: Tai-tech; Manuf_Part_3: BLM18PG121SN1D; Manuf_3: MURATA; Fitted: YES; Ordered_By: Subcon
R43 R58 = Res_0_5%_0603: Resistor,0R,0603,5%,YAGEO; Manuf_Part_1: RC0603JR-070RL; Fitted: YES; Order_Code: 2363481; Ordered_By: subcon
R44 R45 = Res_0_5%_0402: Resistor,0R,0402,5%,YAGEO; Manuf_Part_1: RC0402JR-070RL; Order_Code: 2363467; Ordered_By: Subcon
R46-R48 R50 = Res_0_5%_0402: Resistor,0R,0402,5%,YAGEO; Manuf_Part_1: RC0402JR-070RL; Fitted: YES; Order_Code: 2363467; Ordered_By: Subcon
R49 = Res_0_5%_0402: Resistor,0R,0402,5%,YAGEO; Manuf_Part_1: RC0402JR-070RL; Order_Code: 2363467; Fitted: YES; Ordered_By: Subcon
R51 = Res_56_1%_0402: Resistor,56R,0402,1%,YAGEO; Manuf_Part_1: RC0402FR-0756RL; Fitted: YES; Order_Code: 9239081RL; Ordered_By: Subcon
R52 R55 = Res_10K_1%_0402: Resistor,10K,0402,1%,YAGEO; Manuf_Part_1: RC0402FR-0710KL; Fitted: YES; Ordered_By: subcon
R53 R54 = Res_10K_1%_0402: Resistor,10K,0402,1%,YAGEO; Manuf_Part_1: RC0402FR-0710KL; Ordered_By: subcon
R56 R57 R102 R104 = Res_2K7_1%_0402: Resistor,2K7,0402,1%,YAGEO; Manuf_Part_1: RC0402FR-072K7L; Fitted: YES; Ordered_By: Subcon
U13 = STM32F413ZHT6U: STM32 Tiny Manta 1M5 LQFP144 (STM32F413ZHT6U); Manuf_1: STM; Ref St: 9175122; ECCN_US/EU: 3A991A2/NEC; Fitted: YES
X2 = XTAL_8M_NX3225GD: Crystal 8Mhz, 8pF, -+50PPM, SMD; Manuf_1: NDK; Manuf_Part_1: NX3225GD 8MHz EXS00A-CG04874; ECCN_US/EU: EAR99/NEC; NDK Ref: X3127326; Ref St: 9157029; Ordered_By: STM
X3 = XTAL_32K_NX3215SA: Crystal 32.768kHz, 6pF, -+20PPM, R=50K, SMD; Manuf_1: NDK; Manuf_Part_1: NX3215SA 32.768KHz EXS00A-MU00525; ECCN_US/EU: EAR99/NEC; Ref St: 9157034; NDK Ref: X3101802; Fitted: YES; Ordered_By: STM

## Sheet 01_PSRAM.SchDoc: PSRAM
size A4; Date: 17-03-2016; Author: A.B; CompanyName: STMicroelectronics; Organization: Microcontrollers Division; Address1: 12, Rue Jules HOROWITZ; Address2: 38019 Grenoble; Address3: FRANCE; DocumentNumber: 4; Revision: D-01; SheetNumber: 4; SheetTotal: 12; Project: STM32F413H-DISCO
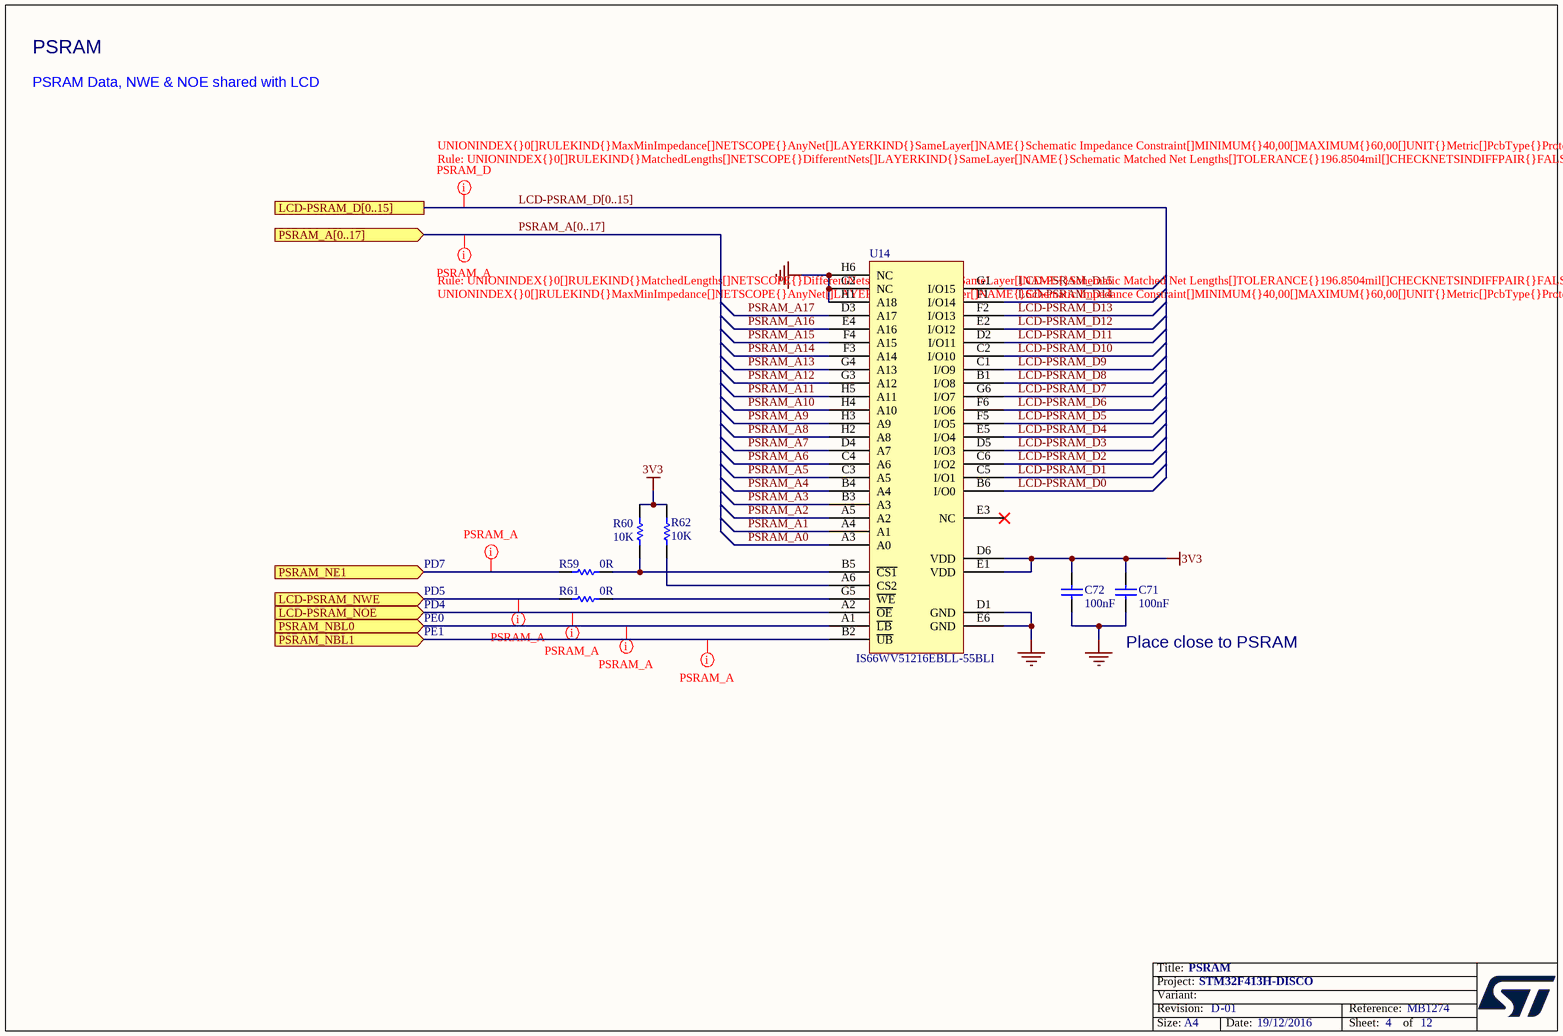
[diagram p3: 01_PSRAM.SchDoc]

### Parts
C71  100nF  [C0402]
C72  100nF  [C0402]
R59  0R  [R0402]
R60  10K  [R0402]
R61  0R  [R0402]
R62  10K  [R0402]
U14  IS66WV51216EBLL-55BLI  [ICC_MINI-BGA48_6X8_P075]

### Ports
LCD-PSRAM_D[0..15], LCD-PSRAM_NOE (in), LCD-PSRAM_NWE (in), PSRAM_A[0..17] (in), PSRAM_NBL0 (in), PSRAM_NBL1 (in), PSRAM_NE1 (in)

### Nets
3V3: C71.2 C72.2 R60.2 R62.2 U14.D6(VDD) U14.E1(VDD)
GND: C71.1 C72.1 U14.D1(GND) U14.E6(GND) U14.G2(NC) U14.H1(A18) U14.H6(NC)
LCD-PSRAM_D0: U14.B6(I/O0)
LCD-PSRAM_D1: U14.C5(I/O1)
LCD-PSRAM_D2: U14.C6(I/O2)
LCD-PSRAM_D3: U14.D5(I/O3)
LCD-PSRAM_D4: U14.E5(I/O4)
LCD-PSRAM_D5: U14.F5(I/O5)
LCD-PSRAM_D6: U14.F6(I/O6)
LCD-PSRAM_D7: U14.G6(I/O7)
LCD-PSRAM_D8: U14.B1(I/O8)
LCD-PSRAM_D9: U14.C1(I/O9)
LCD-PSRAM_D10: U14.C2(I/O10)
LCD-PSRAM_D11: U14.D2(I/O11)
LCD-PSRAM_D12: U14.E2(I/O12)
LCD-PSRAM_D13: U14.F2(I/O13)
LCD-PSRAM_D14: U14.F1(I/O14)
LCD-PSRAM_D15: U14.G1(I/O15)
LCD-PSRAM_NOE: U14.A2(~{OE}) ; port LCD-PSRAM_NOE
LCD-PSRAM_NWE: R61.1 ; port LCD-PSRAM_NWE
PSRAM_A0: U14.A3(A0)
PSRAM_A1: U14.A4(A1)
PSRAM_A2: U14.A5(A2)
PSRAM_A3: U14.B3(A3)
PSRAM_A4: U14.B4(A4)
PSRAM_A5: U14.C3(A5)
PSRAM_A6: U14.C4(A6)
PSRAM_A7: U14.D4(A7)
PSRAM_A8: U14.H2(A8)
PSRAM_A9: U14.H3(A9)
PSRAM_A10: U14.H4(A10)
PSRAM_A11: U14.H5(A11)
PSRAM_A12: U14.G3(A12)
PSRAM_A13: U14.G4(A13)
PSRAM_A14: U14.F3(A14)
PSRAM_A15: U14.F4(A15)
PSRAM_A16: U14.E4(A16)
PSRAM_A17: U14.D3(A17)
PSRAM_NBL0: U14.A1(~{LB}) ; port PSRAM_NBL0
PSRAM_NBL1: U14.B2(~{UB}) ; port PSRAM_NBL1
PSRAM_NE1: R59.1 ; port PSRAM_NE1
NetR59_2: R59.2 R60.1 U14.B5(~{CS1})
NetR61_2: R61.2 U14.G5(~{WE})
NetR62_1: R62.1 U14.A6(CS2)

Not connected (* = marked no-connect by the designer): U14 E3(NC)*

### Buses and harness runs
bus LCD-PSRAM_D[0..15] = port LCD-PSRAM_D[0..15]
bus PSRAM_A[0..17] = port PSRAM_A[0..17]

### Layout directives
rule Matched Net Lengths [Tolerance = 5mm]; rule Impedance Constraint [Min = 40.00    Max = 60.00    ]: (no net found under the mark), LCD-PSRAM_NOE, LCD-PSRAM_NWE, PSRAM_NBL0, PSRAM_NBL1, PSRAM_NE1

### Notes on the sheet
- PSRAM
- PSRAM Data, NWE & NOE shared with LCD
- PD7
- PD5
- PD4
- PE0
- PE1
- (near C71) Place close to PSRAM

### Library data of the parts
C71 C72 = Cap_100nF_X7R_10%_0402: as C50 on sheet 00_MCU
R59 R61 = Res_0_5%_0402: as R46 on sheet 00_MCU
R60 R62 = Res_10K_1%_0402: as R52 on sheet 00_MCU
U14 = IS66WV51216EBLL-55BLI: IC SRAM 8MBIT 55NS 48MINIBGA 6mm x 8mm; Manuf_1: ISSI, Integrated Silicon Solution Inc; Fitted: YES; ECCN_US/EU: EAR99/NEC; Ordered_By: Subcon

## Sheet 02_QSPI.SchDoc: QSPI
size A4; Date: 9/24/2014; Author: P.A.; CompanyName: STMicroelectronics; Organization: Microcontrollers Division; Address1: 12, Rue Jules HOROWITZ; Address2: 38019 Grenoble; Address3: FRANCE; DocumentNumber: 5; Revision: D-01; SheetNumber: 5; SheetTotal: 12; Project: STM32F413H-DISCO
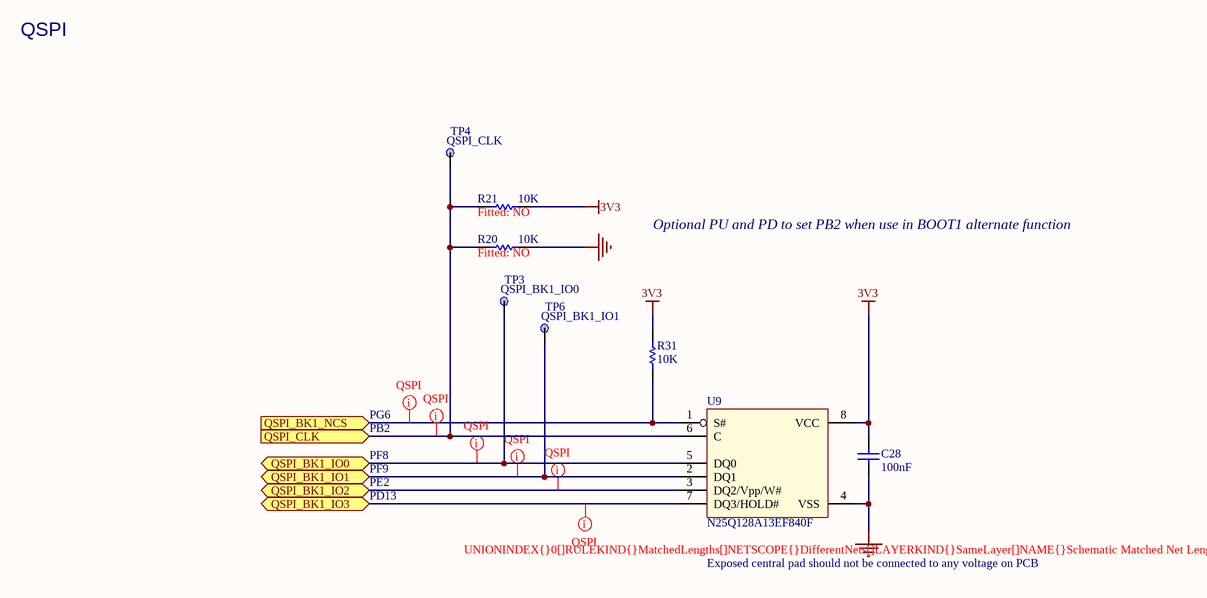
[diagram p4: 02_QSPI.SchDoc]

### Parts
C28  100nF  [C0402]
R20  10K  Fitted: NO  [R0402]
R21  10K  Fitted: NO  [R0402]
R31  10K  [R0402]
TP3  value QSPI_BK1_IO0  [TP_SMD_1MM]  (hidden comment: TP)
TP4  value QSPI_CLK  [TP_SMD_1MM]  (hidden comment: TP)
TP6  value QSPI_BK1_IO1  [TP_SMD_1MM]  (hidden comment: TP)
U9  N25Q128A13EF840F  [ICC_V-PDFN-8_8X6_P127]

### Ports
QSPI_BK1_IO0 (bidir), QSPI_BK1_IO1 (bidir), QSPI_BK1_IO2 (bidir), QSPI_BK1_IO3 (bidir), QSPI_BK1_NCS (in), QSPI_CLK (in)

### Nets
3V3: C28.2 R21.2 R31.2 U9.8(VCC)
GND: C28.1 R20.2 U9.4(VSS)
QSPI_BK1_IO0: TP3.1 U9.5(DQ0) ; port QSPI_BK1_IO0
QSPI_BK1_IO1: TP6.1 U9.2(DQ1) ; port QSPI_BK1_IO1
QSPI_BK1_IO2: U9.3(DQ2/Vpp/W#) ; port QSPI_BK1_IO2
QSPI_BK1_IO3: U9.7(DQ3/HOLD#) ; port QSPI_BK1_IO3
QSPI_BK1_NCS: R31.1 U9.1(S#) ; port QSPI_BK1_NCS
QSPI_CLK: R20.1 R21.1 TP4.1 U9.6(C) ; port QSPI_CLK

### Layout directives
rule Matched Net Lengths [Tolerance = 5mm]: QSPI_BK1_IO0, QSPI_BK1_IO1, QSPI_BK1_IO2, QSPI_BK1_IO3, QSPI_BK1_NCS, QSPI_CLK

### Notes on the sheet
- QSPI
- Optional PU and PD to set PB2 when use in BOOT1 alternate function
- PG6
- PB2
- PF8
- PF9
- PE2
- PD13
- Exposed central pad should not be connected to any voltage on PCB

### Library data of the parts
C28 = Cap_100nF_X7R_10%_0402: as C50 on sheet 00_MCU
R20 R21 = Res_10K_1%_0402: as R53 on sheet 00_MCU
R31 = Res_10K_1%_0402: as R52 on sheet 00_MCU
TP3 TP4 TP6 = TP 1mm: Test Point; Fitted: YES; Ordered_By: Subcon
U9 = N25Q128A13EF840F: 128Mb, 3V, Multiple I/O Serial Flash Memory, Quad/Dual; Manuf_1: MICRON; Manuf_Part_2: N25Q256A13EF840F; Manuf_Part_3: N25Q512A13GF840F; ECCN_US/EU: 3A991/NEC; Ref St: 9171973; Fitted: YES; Order_code: N25Q128A13EF840F-ND; Ordered_By: STM

## Sheet 04_LCD.SchDoc: LCD
size A3; Date: 3/31/2015; Author: P.A.; CompanyName: STMicroelectronics; Organization: Microcontrollers Division; Address1: 12, Rue Jules HOROWITZ; Address2: 38019 Grenoble; Address3: FRANCE; DocumentNumber: 7; Revision: D-01; SheetNumber: 7; SheetTotal: 12; Project: STM32F413H-DISCO
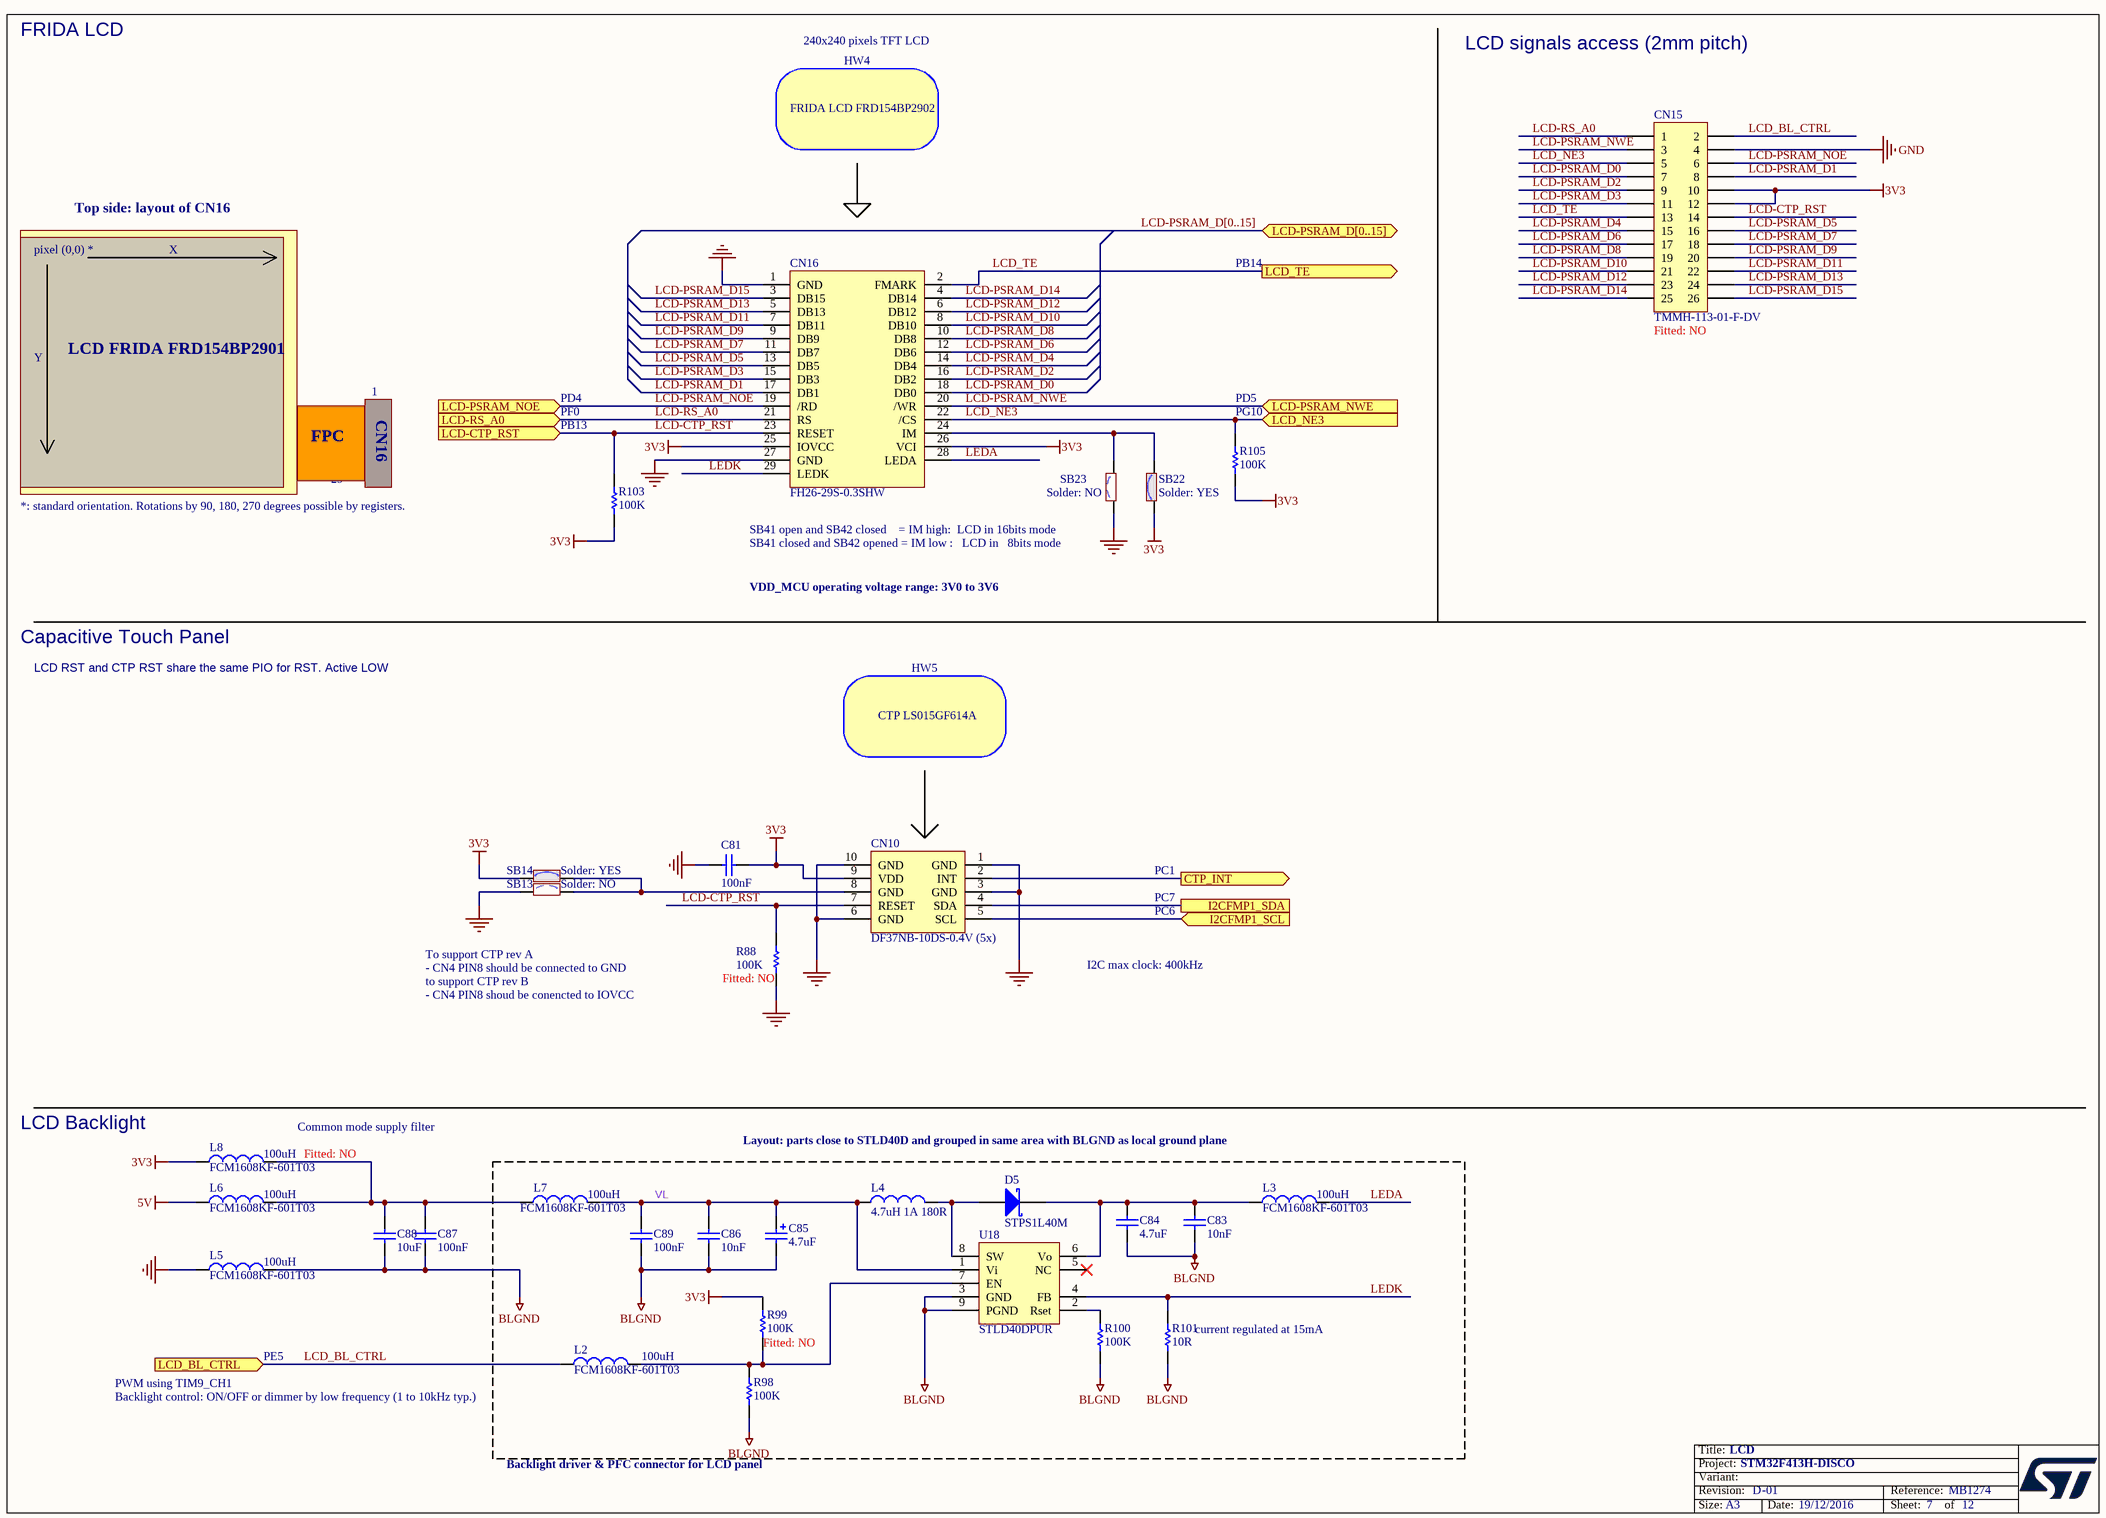
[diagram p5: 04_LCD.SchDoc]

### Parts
C81  100nF  [C0402]
C83  10nF  [C0402]
C84  4.7uF  [C1206]
C85  4.7uF  [CPOL_TAJ-A_1206_H180]
C86  10nF  [C0402]
C87  100nF  [C0402]
C88  10uF  [C0805]
C89  100nF  [C0402]
CN10  DF37NB-10DS-0.4V (5x)  [CON_HRS_DF37NB-10DS-04V]
CN15  TMMH-113-01-F-DV  Fitted: NO  [CON_SAMTEC_TMMH-113-01-F-DV]
CN16  FH26-29S-0.3SHW  [CON_HRS_FH26-29S-03SHW]
D5  STPS1L40M  [DIO_DO216-AA]
HW4  FRIDA LCD FRD154BP2902  (mechanical)
HW5  CTP LS015GF614A  [LCD_DRAWING_PROJET-MB1274]  (mechanical)
L2  100uH  Manuf_Part_1: FCM1608KF-601T03  [L0603]
L3  100uH  Manuf_Part_1: FCM1608KF-601T03  [L0603]
L4  4.7uH 1A 180R  [L1210_LQH]
L5  100uH  Manuf_Part_1: FCM1608KF-601T03  [L0603]
L6  100uH  Manuf_Part_1: FCM1608KF-601T03  [L0603]
L7  100uH  Manuf_Part_1: FCM1608KF-601T03  [L0603]
L8  100uH  Manuf_Part_1: FCM1608KF-601T03  Fitted: NO  [L0603]
R88  100K  Fitted: NO  [R0402]
R98  100K  [R0402]
R99  100K  Fitted: NO  [R0402]
R100  100K  [R0402]
R101  10R  [R0603]
R103  100K  [R0402]
R105  100K  [R0402]
SB13  Solder: NO  [SOLDER-BRIDGE_R0603-0R]  (hidden comment: SB_OFF)
SB14  Solder: YES  [SOLDER-BRIDGE_R0603-0R]  (hidden comment: SB_ON)
SB22  Solder: YES  [SOLDER-BRIDGE_R0603-0R]  (hidden comment: SB_ON)
SB23  Solder: NO  [SOLDER-BRIDGE_R0603-0R]  (hidden comment: SB_OFF)
U18  STLD40DPUR  [ICC_QFN8-EPAD_3X3_P065]

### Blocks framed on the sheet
current regulated at 15mA: C83-C86 C89 D5 L2-L4 L7 R98-R101 U18

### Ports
CTP_INT (out), I2CFMP1_SCL (in), I2CFMP1_SDA, LCD-CTP_RST (in), LCD-PSRAM_D[0..15] (bidir), LCD-PSRAM_NOE (in), LCD-PSRAM_NWE (in), LCD-RS_A0 (in), LCD_BL_CTRL (in), LCD_NE3 (in), LCD_TE (out)

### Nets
3V3: C81.1 CN10.9(VDD) CN15.10 CN15.12 CN16.25(IOVCC) CN16.26(VCI) L8.1 R99.2 R103.1 R105.1 SB14.1 SB22.1
5V: L6.1
BLGND: C83.1 C84.1 C85.2 C86.1 C87.1 C88.1 C89.1 L5.2 R98.1 R100.1 R101.1 U18.3(GND) U18.9(PGND)
GND: C81.2 CN10.1(GND) CN10.3(GND) CN10.6(GND) CN10.10(GND) CN15.4 CN16.1(GND) CN16.27(GND) L5.1 R88.1 SB13.1 SB23.1
CTP_INT: CN10.2(INT) ; port CTP_INT
I2CFMP1_SCL: CN10.5(SCL) ; port I2CFMP1_SCL
I2CFMP1_SDA: CN10.4(SDA) ; port I2CFMP1_SDA
LCD-CTP_RST: CN10.7(RESET) CN15.14 CN16.23(RESET) R88.2 R103.2 ; port LCD-CTP_RST
LCD-PSRAM_D0: CN15.7 CN16.18(DB0)
LCD-PSRAM_D1: CN15.8 CN16.17(DB1)
LCD-PSRAM_D2: CN15.9 CN16.16(DB2)
LCD-PSRAM_D3: CN15.11 CN16.15(DB3)
LCD-PSRAM_D4: CN15.15 CN16.14(DB4)
LCD-PSRAM_D5: CN15.16 CN16.13(DB5)
LCD-PSRAM_D6: CN15.17 CN16.12(DB6)
LCD-PSRAM_D7: CN15.18 CN16.11(DB7)
LCD-PSRAM_D8: CN15.19 CN16.10(DB8)
LCD-PSRAM_D9: CN15.20 CN16.9(DB9)
LCD-PSRAM_D10: CN15.21 CN16.8(DB10)
LCD-PSRAM_D11: CN15.22 CN16.7(DB11)
LCD-PSRAM_D12: CN15.23 CN16.6(DB12)
LCD-PSRAM_D13: CN15.24 CN16.5(DB13)
LCD-PSRAM_D14: CN15.25 CN16.4(DB14)
LCD-PSRAM_D15: CN15.26 CN16.3(DB15)
LCD-PSRAM_NOE: CN15.6 CN16.19(/RD) ; port LCD-PSRAM_NOE
LCD-PSRAM_NWE: CN15.3 CN16.20(/WR) ; port LCD-PSRAM_NWE
LCD-RS_A0: CN15.1 CN16.21(RS) ; port LCD-RS_A0
LCD_BL_CTRL: CN15.2 L2.1 ; port LCD_BL_CTRL
LCD_NE3: CN15.5 CN16.22(/CS) R105.2 ; port LCD_NE3
LCD_TE: CN15.13 CN16.2(FMARK) ; port LCD_TE
LEDA: CN16.28(LEDA) L3.2
LEDK: CN16.29(LEDK) R101.2 U18.4(FB)
VL: C85.1 C86.2 C89.2 L4.1 L7.2 U18.1(Vi)
NetC83_2: C83.2 C84.2 D5.2(K) L3.1 U18.6(Vo)
NetC87_2: C87.2 C88.2 L6.2 L7.1 L8.2
NetCN10_8: CN10.8(GND) SB13.2 SB14.2
NetCN16_24: CN16.24(IM) SB22.2 SB23.2
NetD5_1: D5.1(A) L4.2 U18.8(SW)
NetL2_2: L2.2 R98.2 R99.1 U18.7(EN)
NetR100_2: R100.2 U18.2(Rset)

Not connected (* = marked no-connect by the designer): U18 5(NC)*

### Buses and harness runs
bus LCD-PSRAM_D[0..15] = port LCD-PSRAM_D[0..15]

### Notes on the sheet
- FRIDA LCD
- 240x240 pixels TFT LCD
- LCD signals access (2mm pitch)
- pixel (0,0) *
- Top side: layout of CN16
- X
- PB14
- Y
- LCD FRIDA FRD154BP2901
- FPC
- 1
- CN16
- PD4
- PF0
- PB13
- (near R105) PD5
- (near R105) PG10
- *: standard orientation. Rotations by 90, 180, 270 degrees possible by registers.
- 29
- SB41 open and SB42 closed    = IM high:  LCD in 16bits mode
  SB41 closed and SB42 opened = IM low :   LCD in   8bits mode
- VDD_MCU operating voltage range: 3V0 to 3V6
- Capacitive Touch Panel
- LCD RST and CTP RST share the same PIO for RST. Active LOW
- PC1
- PC6
- PC7
- To support CTP rev A
  - CN4 PIN8 should be connected to GND
  to support CTP rev B
  - CN4 PIN8 shoud be conencted to IOVCC
- I2C max clock: 400kHz
- LCD Backlight
- (near L8) Common mode supply filter
- Layout: parts close to STLD40D and grouped in same area with BLGND as local ground plane
- (near L2) Backlight control: ON/OFF or dimmer by low frequency (1 to 10kHz typ.)
- PWM using TIM9_CH1
- PE5
- Backlight driver & PFC connector for LCD panel

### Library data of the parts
C81 C87 C89 = Cap_100nF_X7R_10%_0402: as C50 on sheet 00_MCU
C83 C86 = Cap_10nF_X7R_10%_0402: Capacitor,10nF,16V,X7R,10%,0402,YAGEO; Manuf_Part_1: CC0402KRX7R7BB103; Fitted: YES; Ordered_By: Subcon
C84 = Cap_4.7uF_X7R_10%_1206: Capacitor,4.7uF,50V, X7R,10%,1206,AVX; Manuf_Part_1: 12065C475KAT2A; Fitted: YES; Ordered_By: Subcon
C85 = Cap_4.7uF_POL_10%_TANA: as C55 on sheet 00_MCU
C88 = Cap_10uF_X5R_10%_0805: Capacitor,10uF,25V,X5R,10%,0805,YAGEO; Manuf_Part_1: CC0805KRX5R8BB106; Fitted: YES; Ordered_By: Subcon
CN10 = DF37NB-10DS-0.4V (5x): Header, 5-Pin, Dual row; Manuf_1: Hirose; Ordered_by: Subcon; Fitted: YES
CN15 = Header TMMH 13X2 2mm (.0787"): 26 Position Receptacle Connector 0.079" (2.00mm) Surface Mount; Manuf_1: SAMTEC; Ordered_By: Subcon
CN16 = FH26-29S-0.3SHW: 29pins FPC connector; Manuf_1: Hirose; Fitted: YES; Ordered_By: Subcon
D5 = STPS1L40M: Low Drop power Schottky rectifier(1A, 40V, 0.4V); Manuf_1: STM; Ref St: 9151085; ECCN_US/EU: EAR99/NEC; Fitted: YES
HW4 = BoM_Item: TFT LCD 240x240 pixels; Ordered_By: Subcon; ECCN_US/EU: EAR99/NEC; Fitted: YES
HW5 = BoM_Item: Self-Capacitive touch Panel; Manuf_Part_1: FRIDA; Ordered_By: Subcon; ECCN_US/EU: EAR99/NEC; Comments: assembled on LCD; Fitted: YES
L2 L3 L5-L7 = BEAD_600R_350MA_0603: as L1 on sheet 00_MCU
L4 = Ind_4.7uH_1A_30%: FIXED IND 4.7UH 1A 180 MOHM 30% SMD; Manuf_Part_1: LQH32PN4R7NN0L; Manuf_1: MURATA; Fitted: YES; Order_Code: 490-5338-1-ND; Ordered_By: Subcon
L8 = BEAD_600R_350MA_0603: Bead,600R,350mA,0603; Manuf_2: TDK; Manuf_Part_2: MPZ1608S300A; Manuf_1: Tai-tech; Manuf_Part_3: BLM18PG121SN1D; Manuf_3: MURATA; Ordered_By: Subcon
R88 R99 = Res_100K_1%_0402: Resistor,100K,0402,1%,YAGEO; Manuf_Part_2: RT0402FRE07100KL; Manuf_Part_1: RC0402FR-07100KL; Ordered_By: Subcon
R98 R100 R103 R105 = Res_100K_1%_0402: Resistor,100K,0402,1%,YAGEO; Manuf_Part_2: RT0402FRE07100KL; Manuf_Part_1: RC0402FR-07100KL; Fitted: YES; Ordered_By: Subcon
R101 = Res_10_1%_0603: Resistor,10R,0603,1%,ROHM,1/4W; Manuf_Part_1: ESR03EZPF10R0; Fitted: YES; Ordered_By: Subcon
SB13 SB23 = SB_OFF: Solder Bridge OFF; Fitted: NO; Ordered_By: Subcon
SB14 SB22 = SB_ON: Solder Bridge ON; Ordered_by: Subcon
U18 = STLD40DPUR: White LED power supply for large display backlight, QFN8; Manuf_1: STM; ECCN_US/EU: EAR99/NEC; Fitted: YES

## Sheet 03_Audio.SchDoc: Audio
size A3; Date: 3/31/2015; Author: P.A.; CompanyName: STMicroelectronics; Organization: Microcontrollers Division; Address1: 12, Rue Jules HOROWITZ; Address2: 38019 Grenoble; Address3: FRANCE; DocumentNumber: 6; Revision: D-01; SheetNumber: 6; SheetTotal: 12; Project: STM32F413H-DISCO
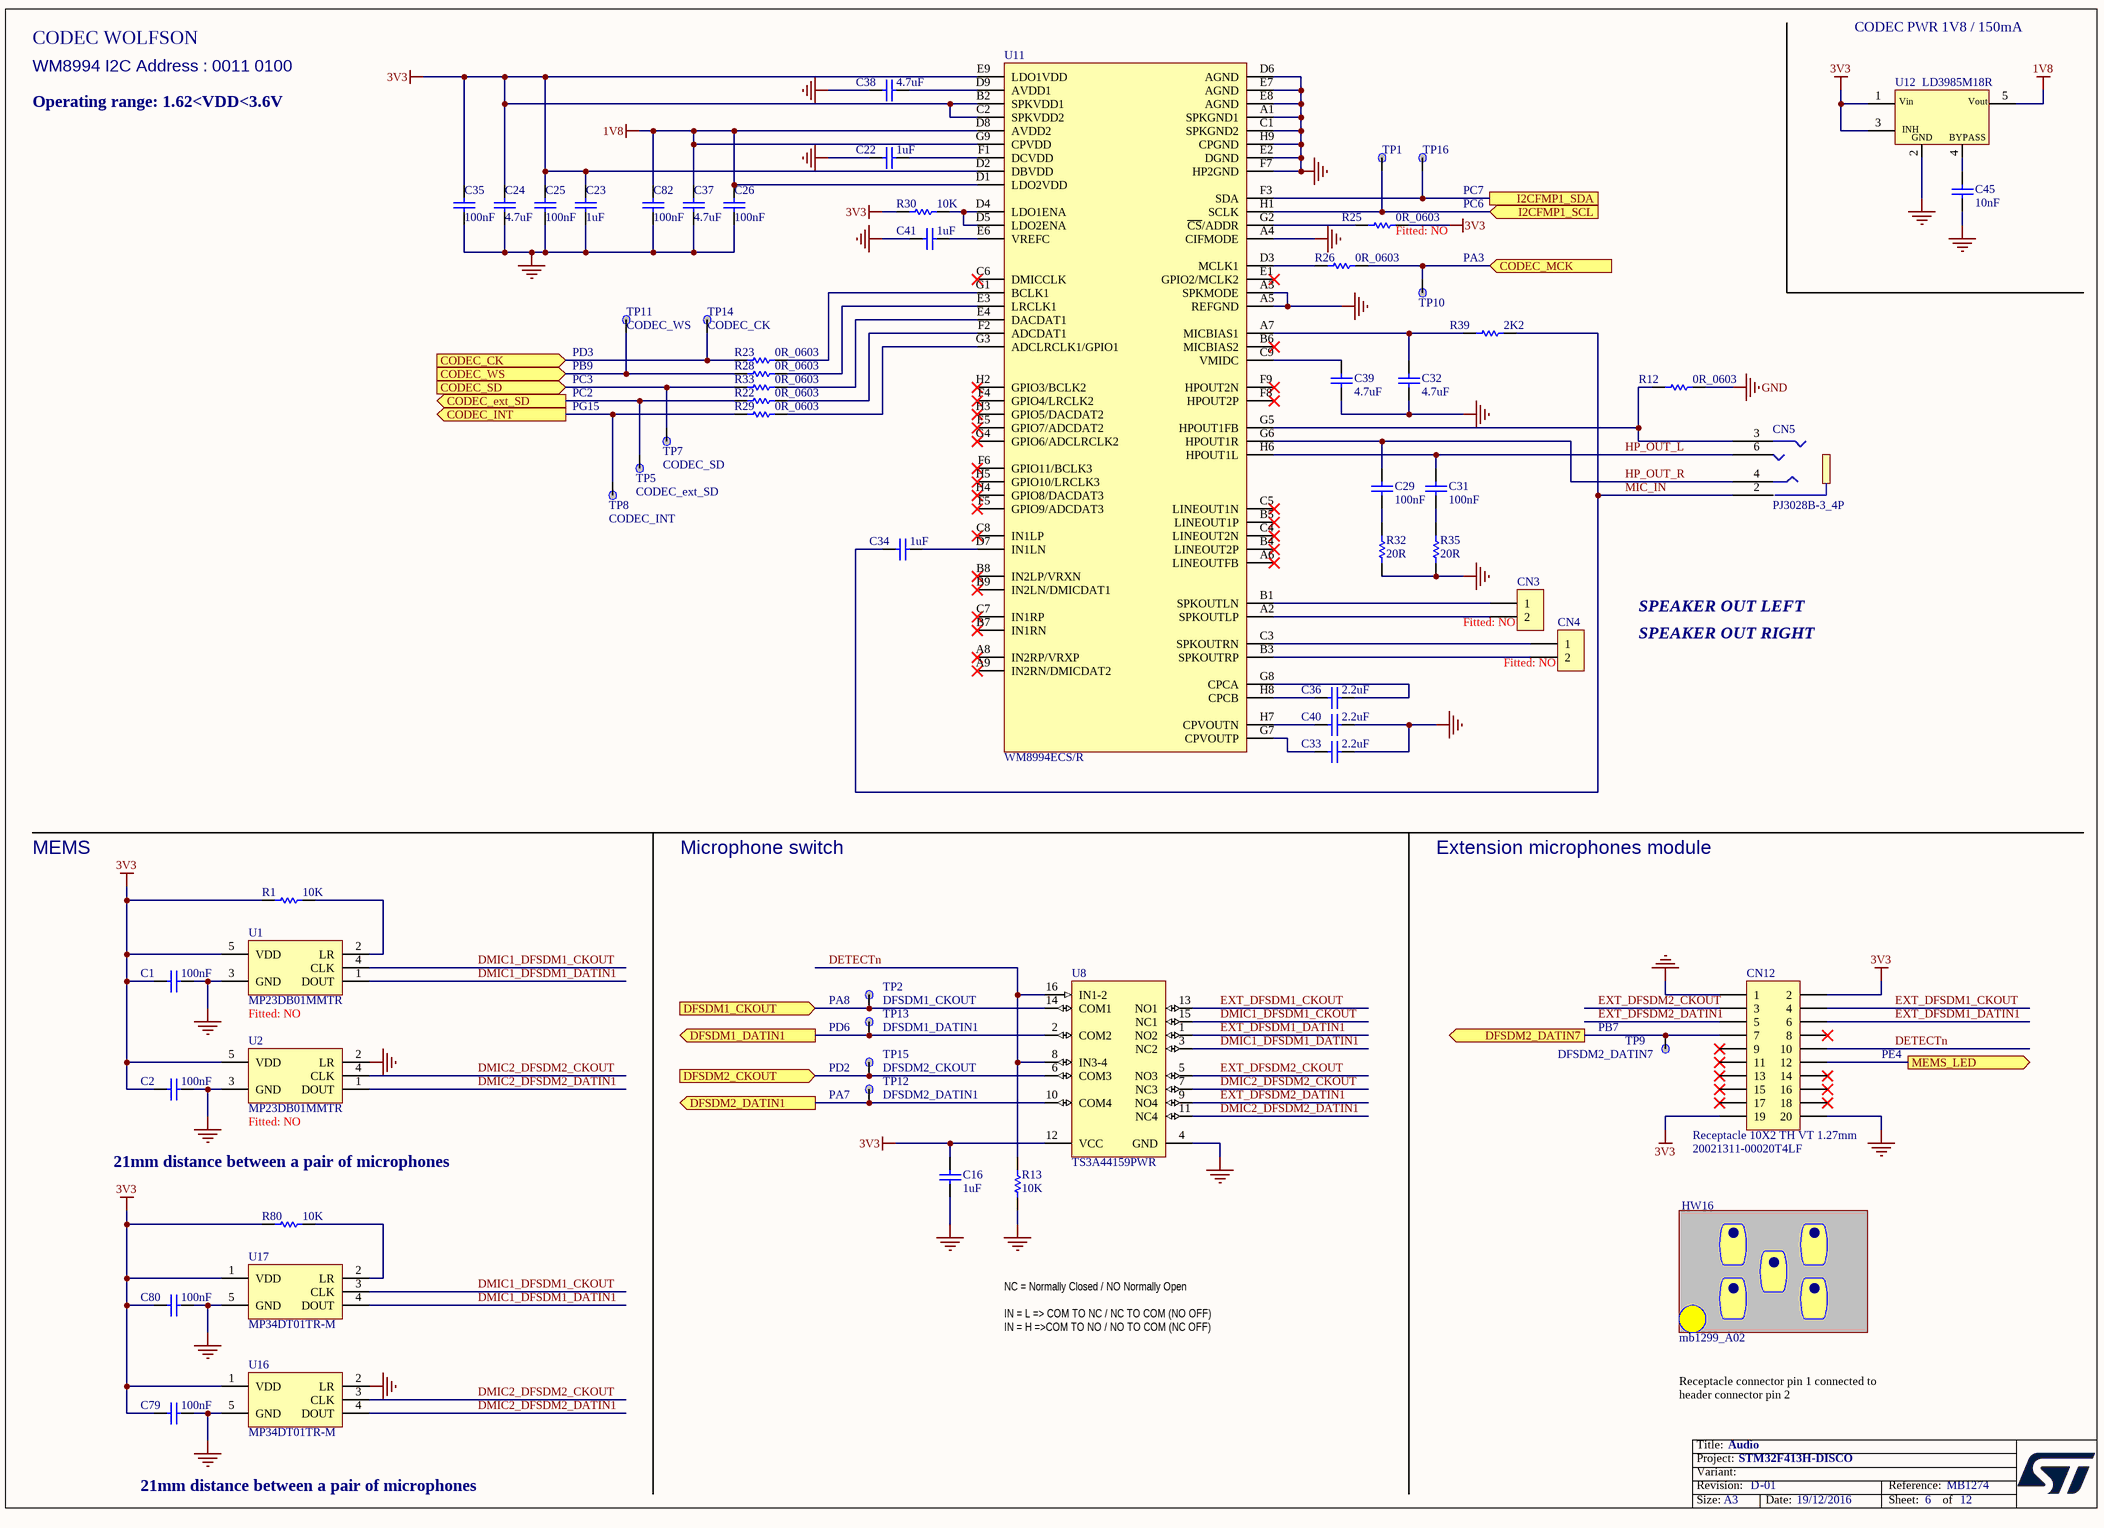
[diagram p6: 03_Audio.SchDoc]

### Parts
C1  100nF  [C0402]
C2  100nF  [C0402]
C16  1uF  [C0603]
C22  1uF  [C0603]
C23  1uF  [C0603]
C24  4.7uF  [C0603]
C25  100nF  [C0402]
C26  100nF  [C0402]
C29  100nF  [C0402]
C31  100nF  [C0402]
C32  4.7uF  [C0603]
C33  2.2uF  [C0603]
C34  1uF  [C0603]
C35  100nF  [C0402]
C36  2.2uF  [C0603]
C37  4.7uF  [C0603]
C38  4.7uF  [C0603]
C39  4.7uF  [C0603]
C40  2.2uF  [C0603]
C41  1uF  [C0603]
C45  10nF  [C0402]
C79  100nF  [C0402]
C80  100nF  [C0402]
C82  100nF  [C0402]
CN3  Fitted: NO  [CON_SAMTEC_TSW-102-07-G-S]  (hidden comment: header 2 pins 2.54mm)
CN4  Fitted: NO  [CON_SAMTEC_TSW-102-07-G-S]  (hidden comment: header 2 pins 2.54mm)
CN5  PJ3028B-3_4P  [CON_PHONE-JACK-3P5_HY_PJ3028B]
CN12  Receptacle 10X2 TH VT 1.27mm  Order_Code: 20021311-00020T4LF
HW16  mb1299_A02  (mechanical)
R1  10K  [R0402]
R12  0R_0603  [R0603]
R13  10K  [R0402]
R22  0R_0603  [R0603]
R23  0R_0603  [R0603]
R25  0R_0603  Fitted: NO  [R0603]
R26  0R_0603  [R0603]
R28  0R_0603  [R0603]
R29  0R_0603  [R0603]
R30  10K  [R0402]
R32  20R  [R0402]
R33  0R_0603  [R0603]
R35  20R  [R0402]
R39  2K2  [R0402]
R80  10K  [R0402]
TP1  TP  [TP_SMD_1MM]  (value not drawn)
TP2  value DFSDM1_CKOUT  [TP_SMD_1MM]  (hidden comment: TP)
TP5  value CODEC_ext_SD  [TP_SMD_1MM]  (hidden comment: TP)
TP7  value CODEC_SD  [TP_SMD_1MM]  (hidden comment: TP)
TP8  value CODEC_INT  [TP_SMD_1MM]  (hidden comment: TP)
TP9  value DFSDM2_DATIN7  [TP_SMD_1MM]  (hidden comment: TP)
TP10  TP  [TP_SMD_1MM]  (value not drawn)
TP11  value CODEC_WS  [TP_SMD_1MM]  (hidden comment: TP)
TP12  value DFSDM2_DATIN1  [TP_SMD_1MM]  (hidden comment: TP)
TP13  value DFSDM1_DATIN1  [TP_SMD_1MM]  (hidden comment: TP)
TP14  value CODEC_CK  [TP_SMD_1MM]  (hidden comment: TP)
TP15  value DFSDM2_CKOUT  [TP_SMD_1MM]  (hidden comment: TP)
TP16  TP  [TP_SMD_1MM]  (value not drawn)
U1  MP23DB01MMTR  Fitted: NO  [MIC_STM_MP23DB01MMTR]
U2  MP23DB01MMTR  Fitted: NO  [MIC_STM_MP23DB01MMTR]
U8  TS3A44159PWR  [ICC_TSSOP16_5P1X4P5_P065]
U11  WM8994ECS/R  [ICC_W-CSP-BGA72_4P511X4P023_P050]
U12  LD3985M18R  [REG_SOT23-5L]
U16  MP34DT01TR-M  [MIC_HCLGA_3X4X1_4LD]
U17  MP34DT01TR-M  [MIC_HCLGA_3X4X1_4LD]

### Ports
CODEC_CK (in), CODEC_ext_SD (out), CODEC_INT (out), CODEC_MCK (in), CODEC_SD (in), CODEC_WS (in), DFSDM1_CKOUT (in), DFSDM1_DATIN1 (out), DFSDM2_CKOUT (in), DFSDM2_DATIN1 (out), DFSDM2_DATIN7 (out), I2CFMP1_SCL (in), I2CFMP1_SDA, MEMS_LED (out)

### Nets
1V8: C26.2 C37.2 C82.2 U11.D1(LDO2VDD) U11.D8(AVDD2) U11.G9(CPVDD) U12.5(Vout)
3V3: C1.2 C2.2 C16.2 C23.2 C24.2 C25.2 C35.2 C79.2 C80.2 CN12.2 CN12.19 R1.1 R25.2 R30.1 R80.1 U1.5(VDD) U2.5(VDD) U8.12(VCC) U11.B2(SPKVDD1) U11.C2(SPKVDD2) U11.D2(DBVDD) U11.E9(LDO1VDD) U12.1(Vin) U12.3(CE) U16.1(VDD) U17.1(VDD)
GND: C1.1 C2.1 C16.1 C22.1 C23.1 C24.1 C25.1 C26.1 C32.1 C33.2 C35.1 C37.1 C38.1 C39.1 C40.2 C41.1 C45.1 C79.1 C80.1 C82.1 CN12.1 CN12.20 R12.2 R13.1 R32.1 R35.1 U1.3(GND) U2.2(LR) U2.3(GND) U8.4(GND) U11.A1(SPKGND1) U11.A3(SPKMODE) U11.A4(CIFMODE) U11.A5(REFGND) U11.C1(SPKGND2) U11.D6(AGND) U11.E2(DGND) U11.E7(AGND) U11.E8(AGND) U11.F7(HP2GND) U11.H9(CPGND) U12.2(GND) U16.2(LR) U16.5(GND) U17.5(GND)
CODEC_CK: R23.1 TP14.1 ; port CODEC_CK
CODEC_ext_SD: R22.1 TP5.1 ; port CODEC_ext_SD
CODEC_INT: R29.1 TP8.1 ; port CODEC_INT
CODEC_MCK: R26.2 TP10.1 ; port CODEC_MCK
CODEC_SD: R33.1 TP7.1 ; port CODEC_SD
CODEC_WS: R28.1 TP11.1 ; port CODEC_WS
DETECTn: CN12.10 R13.2 U8.8(IN3-4) U8.16(IN1-2)
DFSDM1_CKOUT: TP2.1 U8.14(COM1) ; port DFSDM1_CKOUT
DFSDM1_DATIN1: TP13.1 U8.2(COM2) ; port DFSDM1_DATIN1
DFSDM2_CKOUT: TP15.1 U8.6(COM3) ; port DFSDM2_CKOUT
DFSDM2_DATIN1: TP12.1 U8.10(COM4) ; port DFSDM2_DATIN1
DFSDM2_DATIN7: CN12.7 TP9.1 ; port DFSDM2_DATIN7
DMIC1_DFSDM1_CKOUT: U1.4(CLK) U8.15(NC1) U17.3(CLK)
DMIC1_DFSDM1_DATIN1: U1.1(DOUT) U8.3(NC2) U17.4(DOUT)
DMIC2_DFSDM2_CKOUT: U2.4(CLK) U8.7(NC3) U16.3(CLK)
DMIC2_DFSDM2_DATIN1: U2.1(DOUT) U8.11(NC4) U16.4(DOUT)
EXT_DFSDM1_CKOUT: CN12.4 U8.13(NO1)
EXT_DFSDM1_DATIN1: CN12.6 U8.1(NO2)
EXT_DFSDM2_CKOUT: CN12.3 U8.5(NO3)
EXT_DFSDM2_DATIN1: CN12.5 U8.9(NO4)
HP_OUT_L: C31.2 CN5.6 U11.H6(HPOUT1L)
HP_OUT_R: C29.2 CN5.4 U11.G6(HPOUT1R)
I2CFMP1_SCL: TP1.1 U11.H1(SCLK) ; port I2CFMP1_SCL
I2CFMP1_SDA: TP16.1 U11.F3(SDA) ; port I2CFMP1_SDA
MEMS_LED: CN12.12 ; port MEMS_LED
MIC_IN: C34.1 CN5.2 R39.2
NetC22_2: C22.2 U11.F1(DCVDD)
NetC29_1: C29.1 R32.2
NetC31_1: C31.1 R35.2
NetC32_2: C32.2 R39.1 U11.A7(MICBIAS1)
NetC33_1: C33.1 U11.G7(CPVOUTP)
NetC34_2: C34.2 U11.D7(IN1LN)
NetC36_1: C36.1 U11.H8(CPCB)
NetC36_2: C36.2 U11.G8(CPCA)
NetC38_2: C38.2 U11.D9(AVDD1)
NetC39_2: C39.2 U11.C9(VMIDC)
NetC40_1: C40.1 U11.H7(CPVOUTN)
NetC41_2: C41.2 U11.E6(VREFC)
NetC45_2: C45.2 U12.4(BYPASS)
NetCN3_1: CN3.1 U11.B1(SPKOUTLN)
NetCN3_2: CN3.2 U11.A2(SPKOUTLP)
NetCN4_1: CN4.1 U11.C3(SPKOUTRN)
NetCN4_2: CN4.2 U11.B3(SPKOUTRP)
NetCN5_3: CN5.3 R12.1 U11.G5(HPOUT1FB)
NetR1_2: R1.2 U1.2(LR)
NetR22_2: R22.2 U11.F2(ADCDAT1)
NetR23_2: R23.2 U11.G1(BCLK1)
NetR25_1: R25.1 U11.G2(~{CS}/ADDR)
NetR26_1: R26.1 U11.D3(MCLK1)
NetR28_2: R28.2 U11.E3(LRCLK1)
NetR29_2: R29.2 U11.G3(ADCLRCLK1/GPIO1)
NetR30_2: R30.2 U11.D4(LDO1ENA) U11.D5(LDO2ENA)
NetR33_2: R33.2 U11.E4(DACDAT1)
NetR80_2: R80.2 U17.2(LR)

Not connected (* = marked no-connect by the designer): CN12 8* 9* 11* 13* 14* 15* 16* 17* 18*; U11 A6(LINEOUTFB)* A8(IN2RP/VRXP)* A9(IN2RN/DMICDAT2)* B4(LINEOUT2P)* B5(LINEOUT1P)* B6(MICBIAS2)* B7(IN1RN)* B8(IN2LP/VRXN)* B9(IN2LN/DMICDAT1)* C4(LINEOUT2N)* C5(LINEOUT1N)* C6(DMICCLK)* C7(IN1RP)* C8(IN1LP)* E1(GPIO2/MCLK2)* E5(GPIO7/ADCDAT2)* F4(GPIO4/LRCLK2)* F5(GPIO9/ADCDAT3)* F6(GPIO11/BCLK3)* F8(HPOUT2P)* F9(HPOUT2N)* G4(GPIO6/ADCLRCLK2)* H2(GPIO3/BCLK2)* H3(GPIO5/DACDAT2)* H4(GPIO8/DACDAT3)* H5(GPIO10/LRCLK3)*

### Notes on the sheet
- CODEC WOLFSON
- CODEC PWR 1V8 / 150mA
- Operating range: 1.62<VDD<3.6V
- WM8994 I2C Address : 0011 0100
- PC6
- PC7
- PA3
- (near TP11) PD3
- PB9
- PC3
- PG15
- PC2
- SPEAKER OUT RIGHT
- SPEAKER OUT LEFT
- MEMS
- Microphone switch
- Extension microphones module
- PA8
- PD6
- (near TP9) PB7
- PE4
- PD2
- PA7
- 21mm distance between a pair of microphones
- NC = Normally Closed / NO Normally Open
  IN = L => COM TO NC / NC TO COM (NO OFF)
  IN = H =>COM TO NO / NO TO COM (NC OFF)
- Receptacle connector pin 1 connected to header connector pin 2

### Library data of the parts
C1 C2 C25 C26 C29 C31 C35 C79 C80 C82 = Cap_100nF_X7R_10%_0402: as C50 on sheet 00_MCU
C16 C22 C23 C34 C41 = Cap_1uF_X5R_10%_0603: Capacitor,1uF,16V,X5R,10%,0603,YAGEO; Manuf_Part_1: CC0603KRX5R7BB105; Fitted: YES; Ordered_By: Subcon
C24 C32 C37-C39 = Cap_4.7uF_X5R_10%_0603: Capacitor,4.7uF,16V, X5R,10%,0603,YAGEO; Manuf_Part_1: CC0603KRX5R7BB475; Fitted: YES; Order_Code: CC0603KRX5R7BB105; Ordered_By: subcon
C33 C36 C40 = Cap_2.2uF_X5R_10%_0603: Capacitor,2.2uF,10V, X5R,10%,0603,YAGEO; Manuf_Part_1: CC0603KRX5R6BB225; Manuf_Part_2: C0603C225K8PACTU; Manuf_2: KEMET; Fitted: YES; Ordered_By: Subcon
C45 = Cap_10nF_X7R_10%_0402: as C83 on sheet 04_LCD
CN3 CN4 = Header 2 pins: Manuf_1: SAMTEC; Manuf_Part_2: 4711955140470; Manuf_2: KONTEC; Manuf_Part_1: TSW-102-07-x-S; Order_Code: 423-2841; Ordered_By: Subcon
CN5 = MCD-00263: Connector Jack Stereo 3.5mm, female SMT, 4 PIN; Provided_By: Subcon
CN12 = Receptacle 10X2 TH VT 1.27mm: 20 Position Receptacle Connector 0.050" (1.27mm) Through Hole Vertical Mount; Manuf_1: AMPHEMOL_FCI; Fitted: YES; Ordered_By: Subcon
HW16 = mb1299_MEMS_Module: mb1299_MEMS module; Ordered_By: Subcon; Fitted: YES
R1 R13 R30 R80 = Res_10K_1%_0402: as R52 on sheet 00_MCU
R12 R22 R23 R26 R28 R29 R33 = Res_0_5%_0603: as R43 on sheet 00_MCU
R25 = Res_0_5%_0603: Resistor,0R,0603,5%,YAGEO; Manuf_Part_1: RC0603JR-070RL; Order_Code: 2363481; Ordered_By: subcon
R32 R35 = Res_20_1%_0402: Resistor,20R,0402,1%,YAGEO; Manuf_Part_1: RC0402FR-0720RL; Fitted: Yes; Ordered_By: Subcon
R39 = Res_2K2_1%_0402: Resistor,2K2,0402,1%,YAGEO; Manuf_Part_1: RC0402FR-072K2L; Fitted: YES; Ordered_By: Subcon
TP1 = TP 1mm: Test Point; Fitted: YES; Ordered_By: Subcon; Value: I2CFMP1_SCL
TP2 TP5 TP7-TP9 TP11-TP15 = TP 1mm: as TP3 on sheet 02_QSPI
TP10 = TP 1mm: Test Point; Fitted: YES; Ordered_By: Subcon; Value: CODEC_MCK
TP16 = TP 1mm: Test Point; Fitted: YES; Ordered_By: Subcon; Value: I2CFMP1_SDA
U1 U2 = MP23DB01MMTR: MEMS audio sensor, omnidirectional digital microphone; Manuf_1: STM; Ref St: 9188010; ECCN_US/EU: EAR99/NEC
U8 = TS3A44159PWR: SPDT analog switch 4-Channel 2:1 bidirectional; Manuf_1: TI; Fitted: YES; ECCN_US/EU: EAR99/NEC; Order_Code: 1755573; Ordered_By: Subcon
U11 = WM8994ECS/R: Multi-Channel Audio Hub CODEC for Smartphones; Manuf_1: Cirrus Logic; ECCN_US/EU: EAR99/NEC; Fitted: YES; Ordered_By: Subcon
U12 = LD3985M18R: Ultra low drop-low noise BiCMOS voltage, regulators low ESR capacitors compatible; Manuf_1: STM; ECCN_US/EU: EAR99/NEC; Fitted: YES
U16 U17 = MP34DT01TR-M: MEMS audio sensor, omnidirectional digital microphone; Manuf_1: STM; Ref St: 9188008; ECCN_US/EU: EAR99/NEC; Fitted: YES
